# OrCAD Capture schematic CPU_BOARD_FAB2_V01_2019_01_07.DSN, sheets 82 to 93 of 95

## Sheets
82 072 ISOLATOR_2: size B
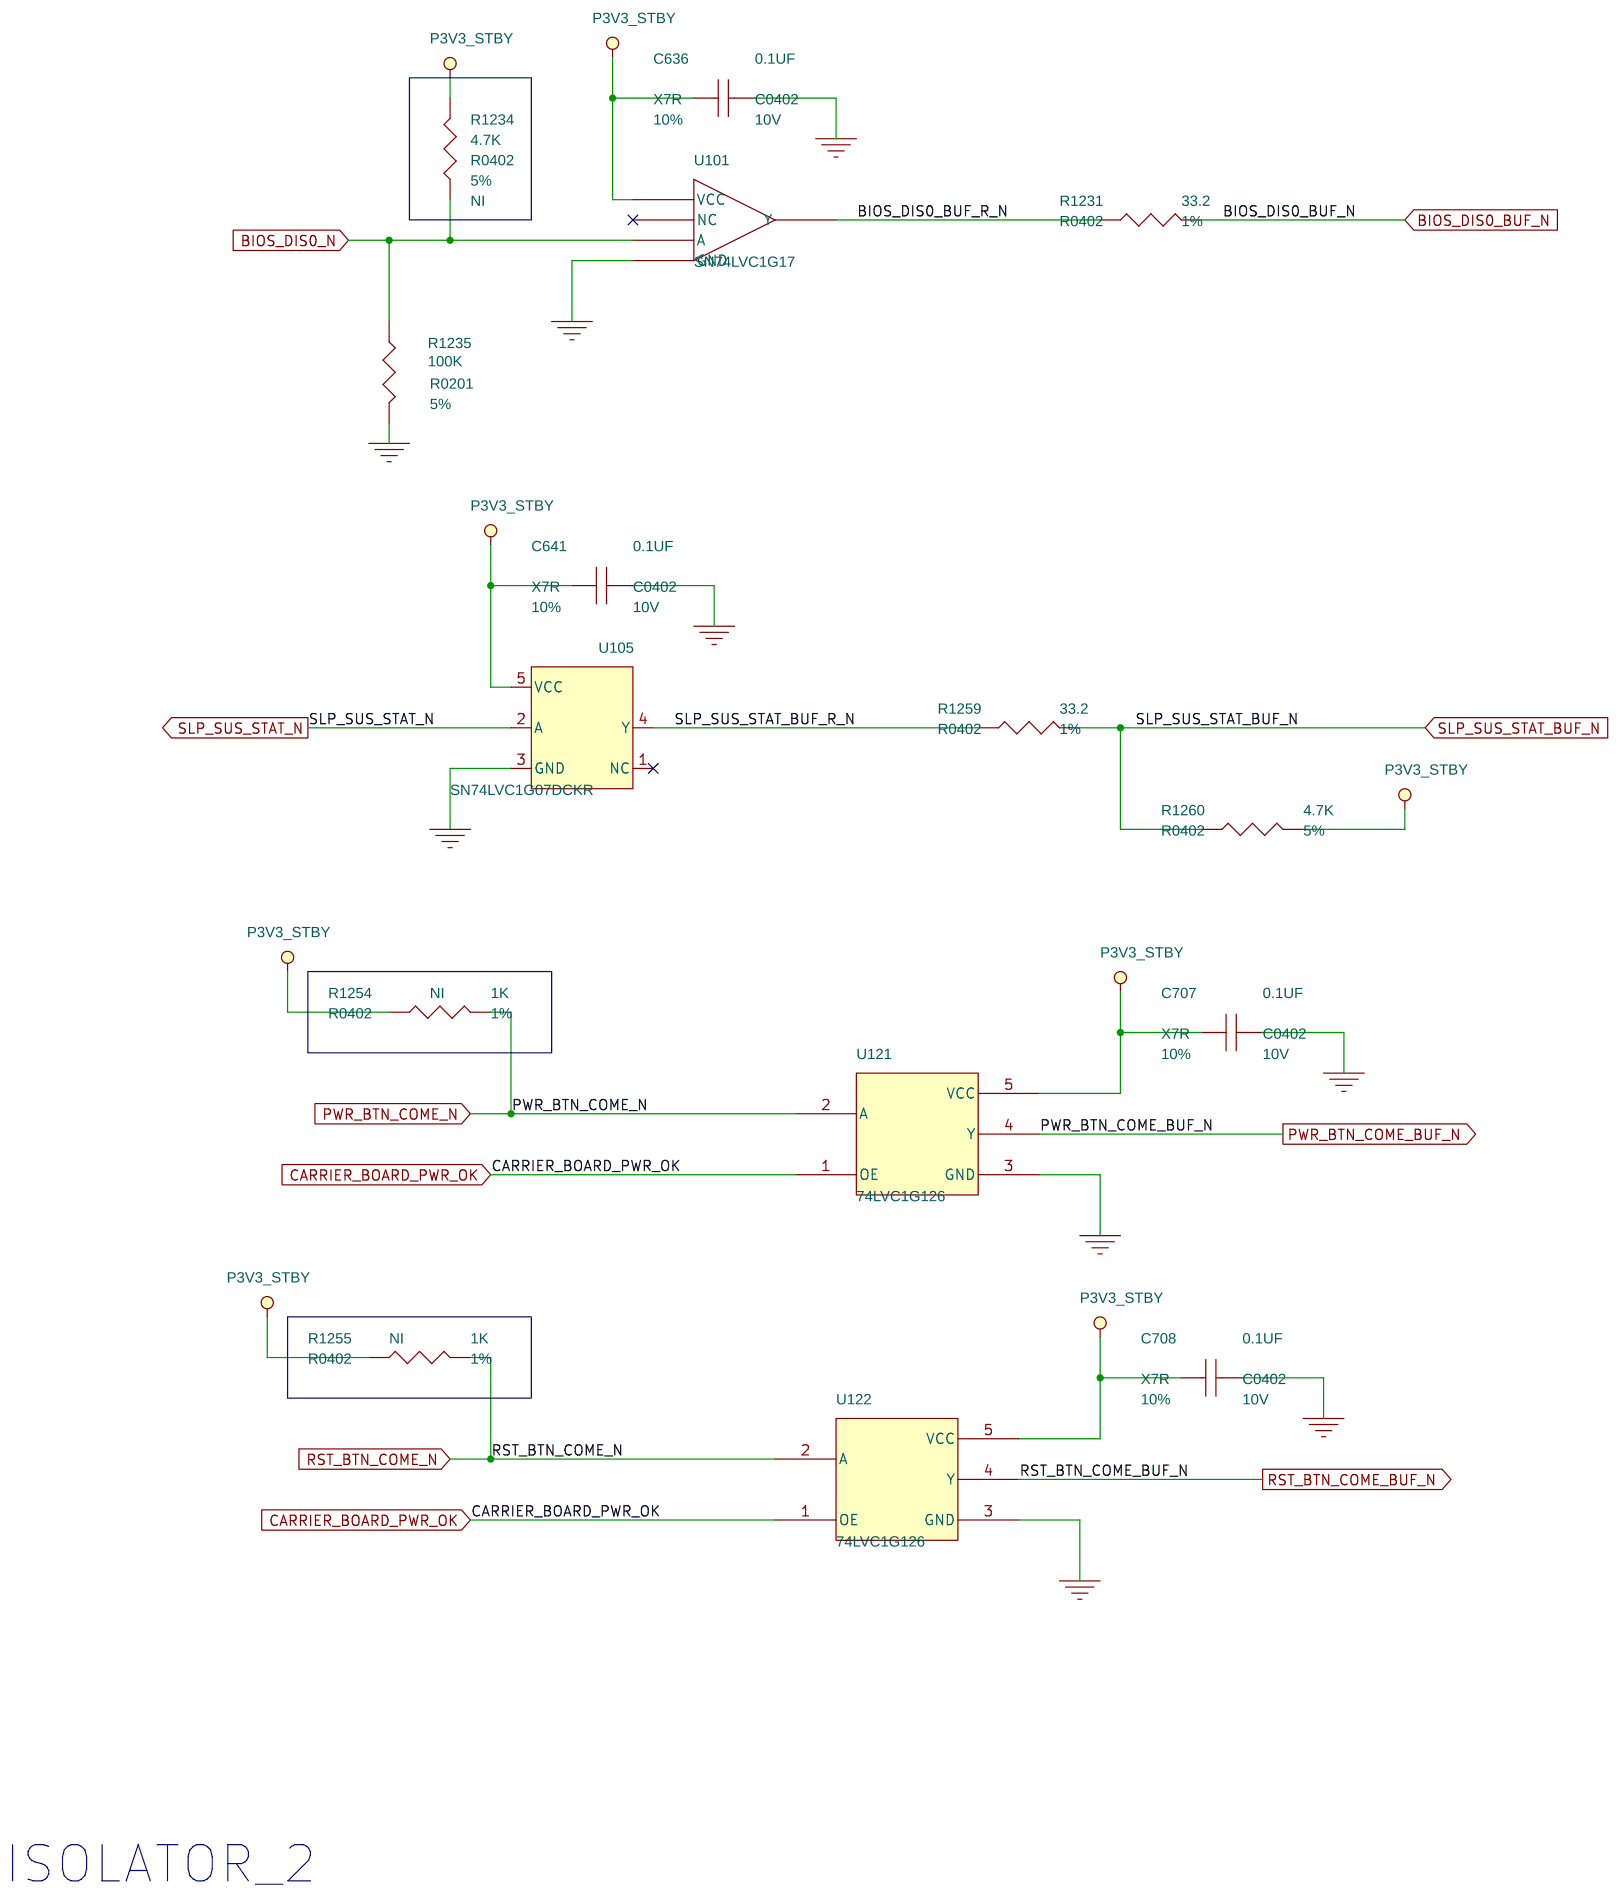
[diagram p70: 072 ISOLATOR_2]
83 077 SCREW: size B
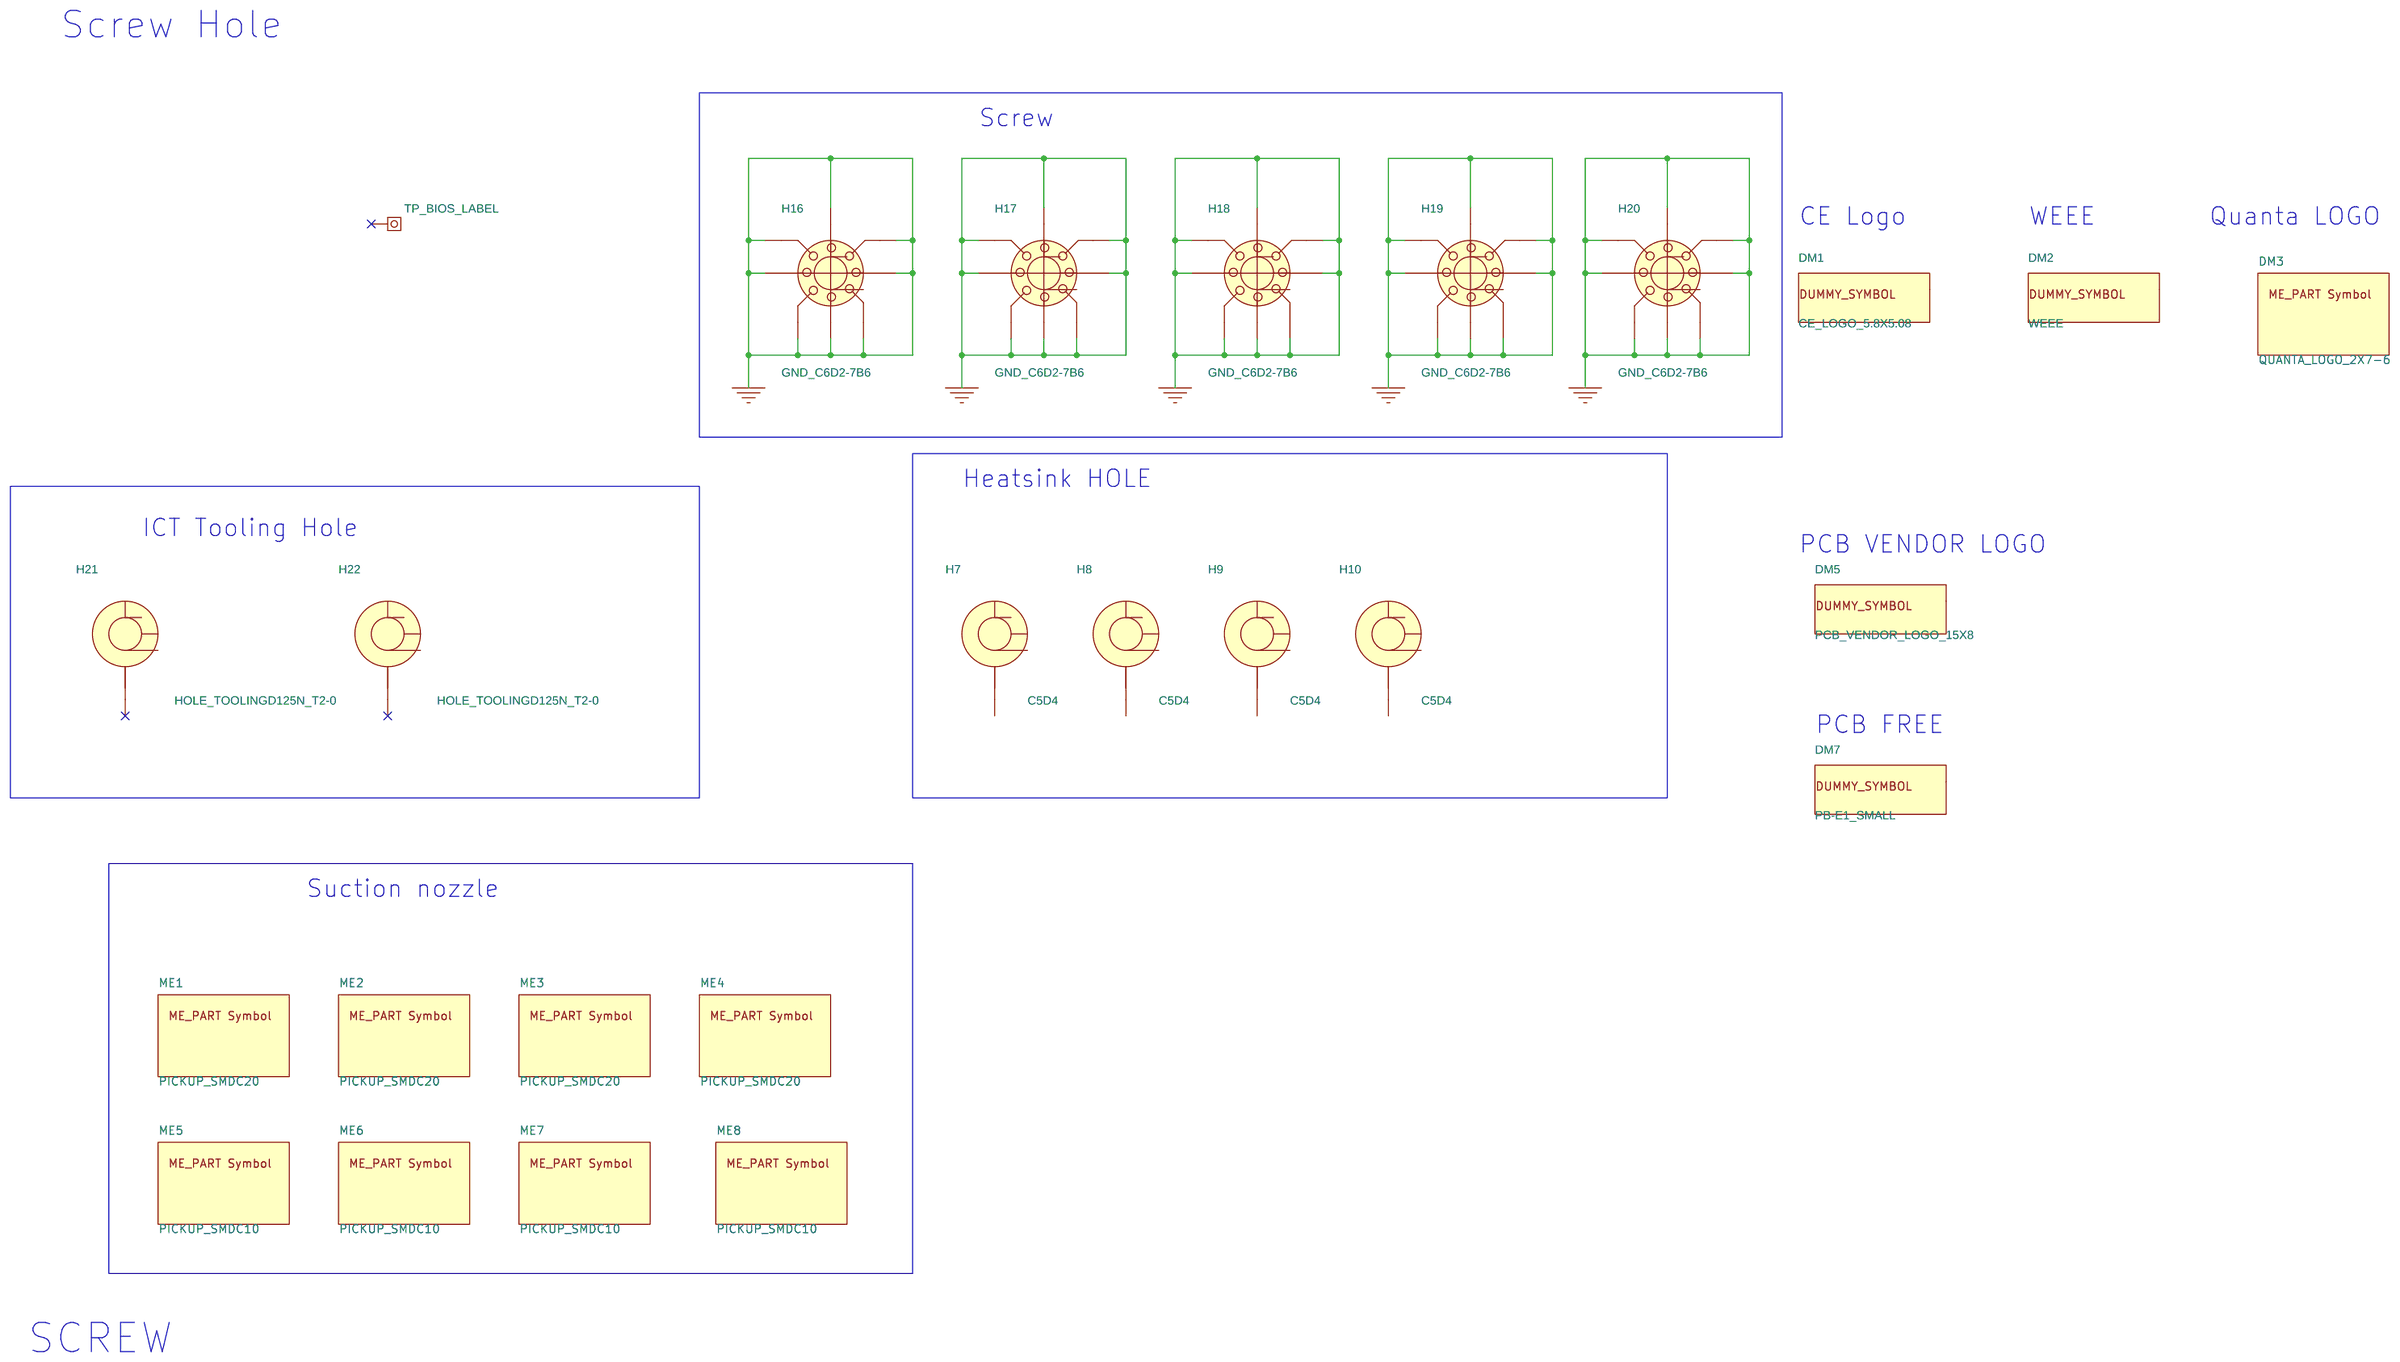
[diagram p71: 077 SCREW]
84 091 P1V05_PCH SWITCH: size B
85 092 BLANK
86 074 POWER SENSING INA230: size B
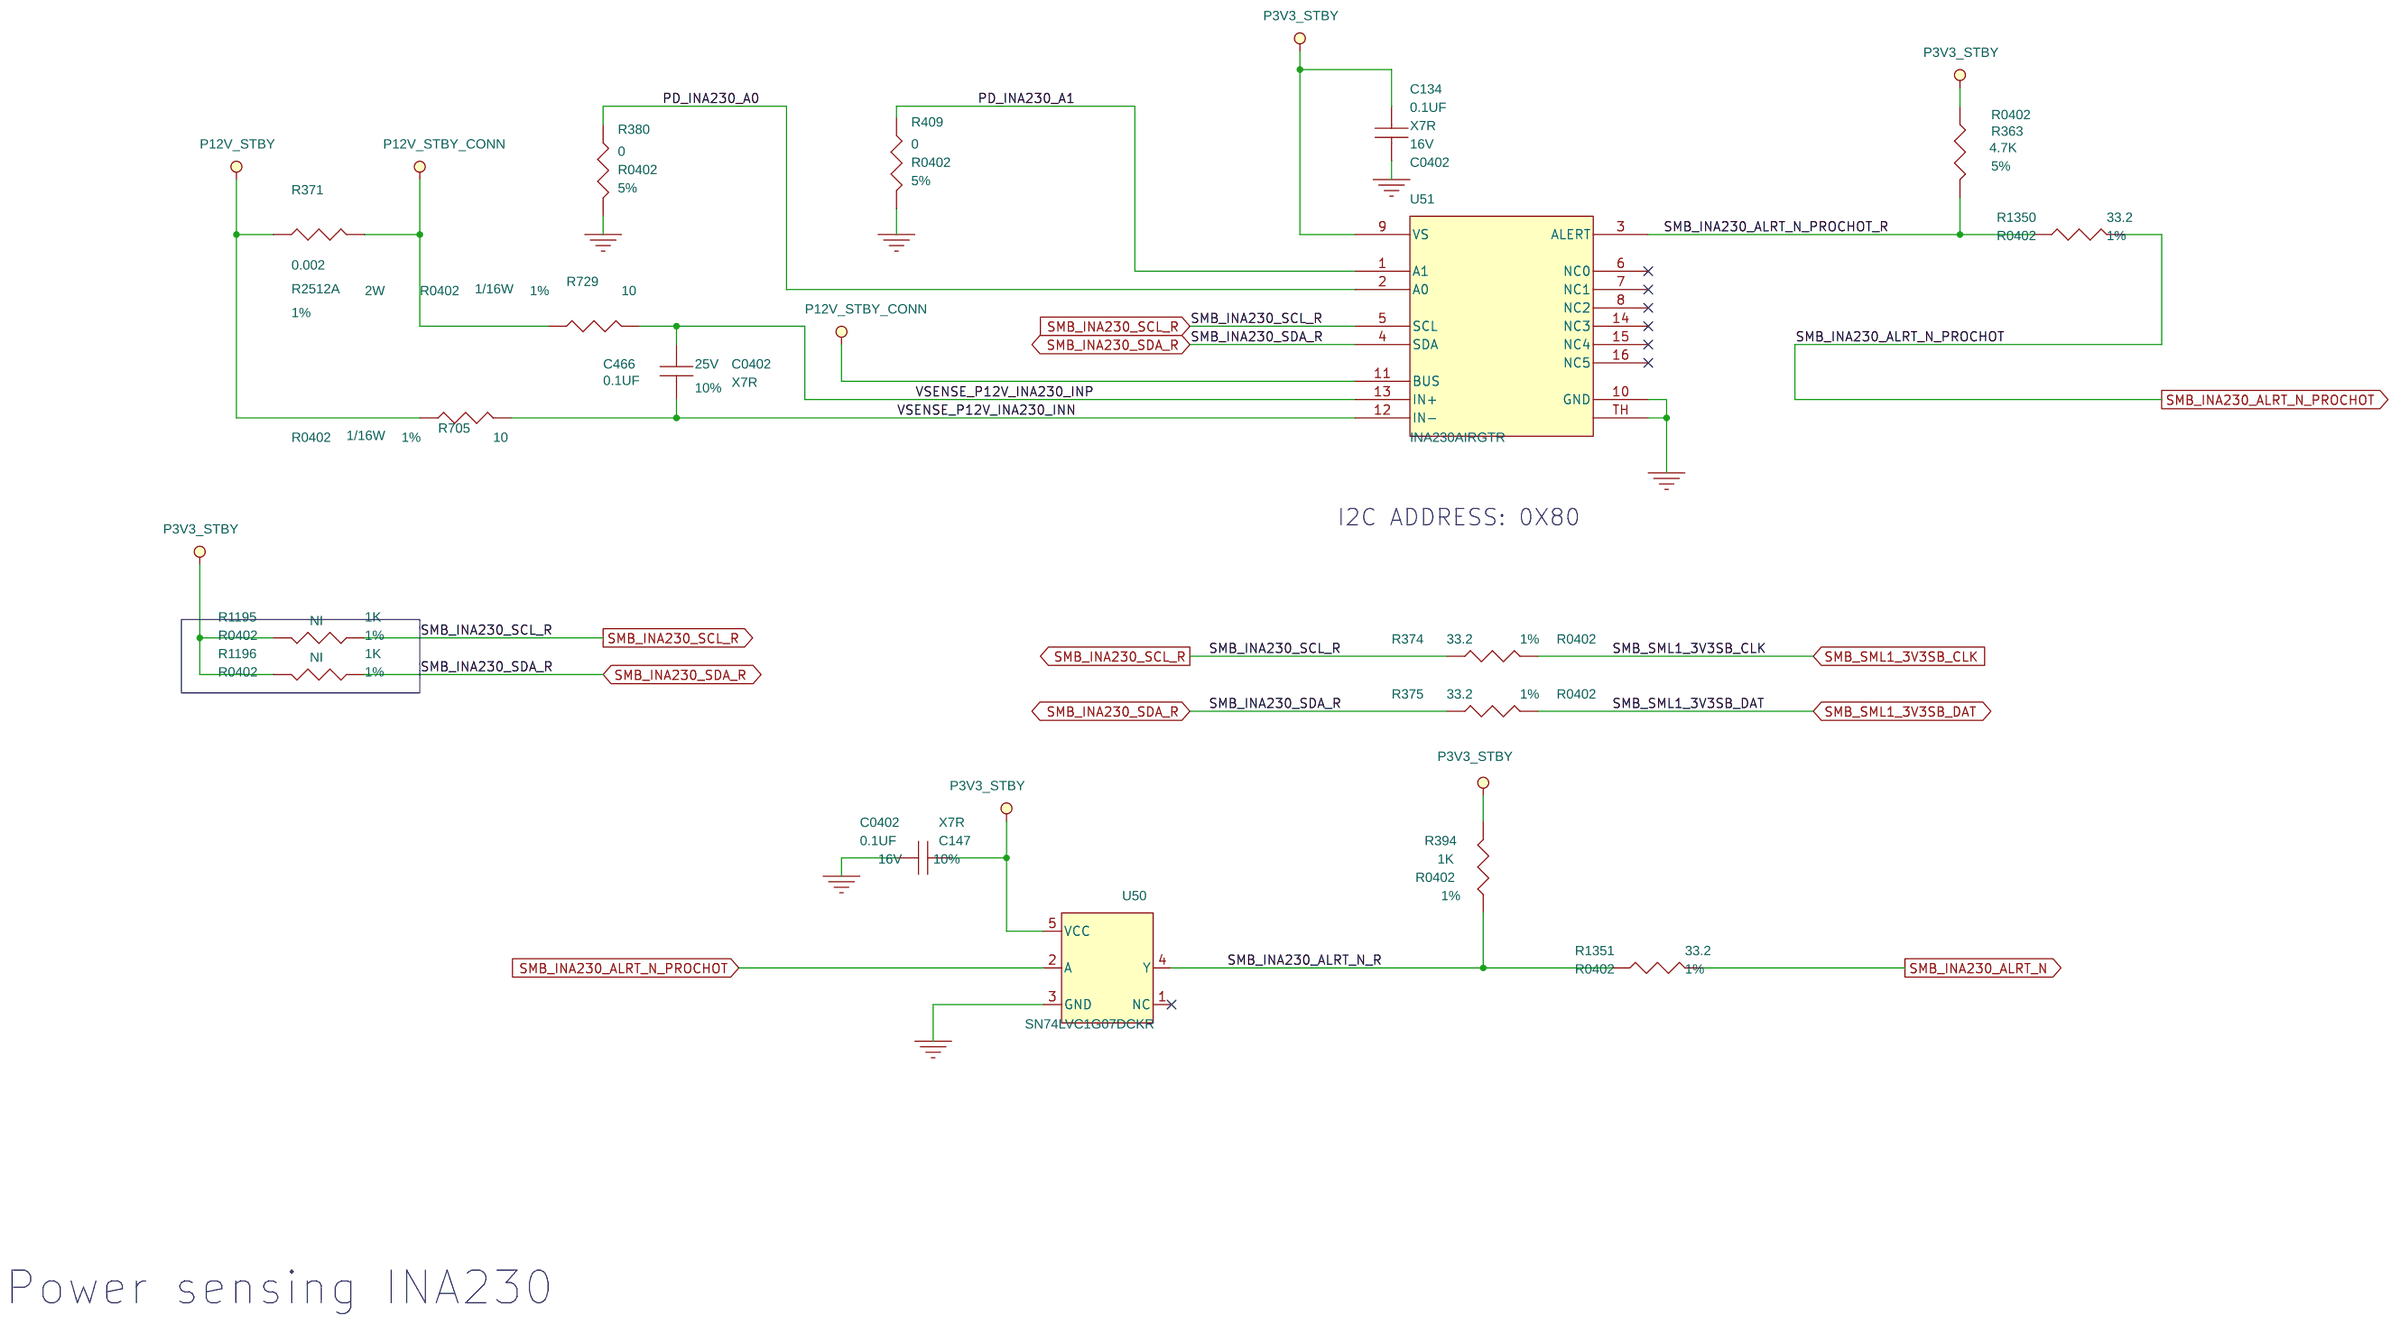
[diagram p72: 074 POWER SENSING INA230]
87 075 I210 GbE PHY PCIE,MDI: size B
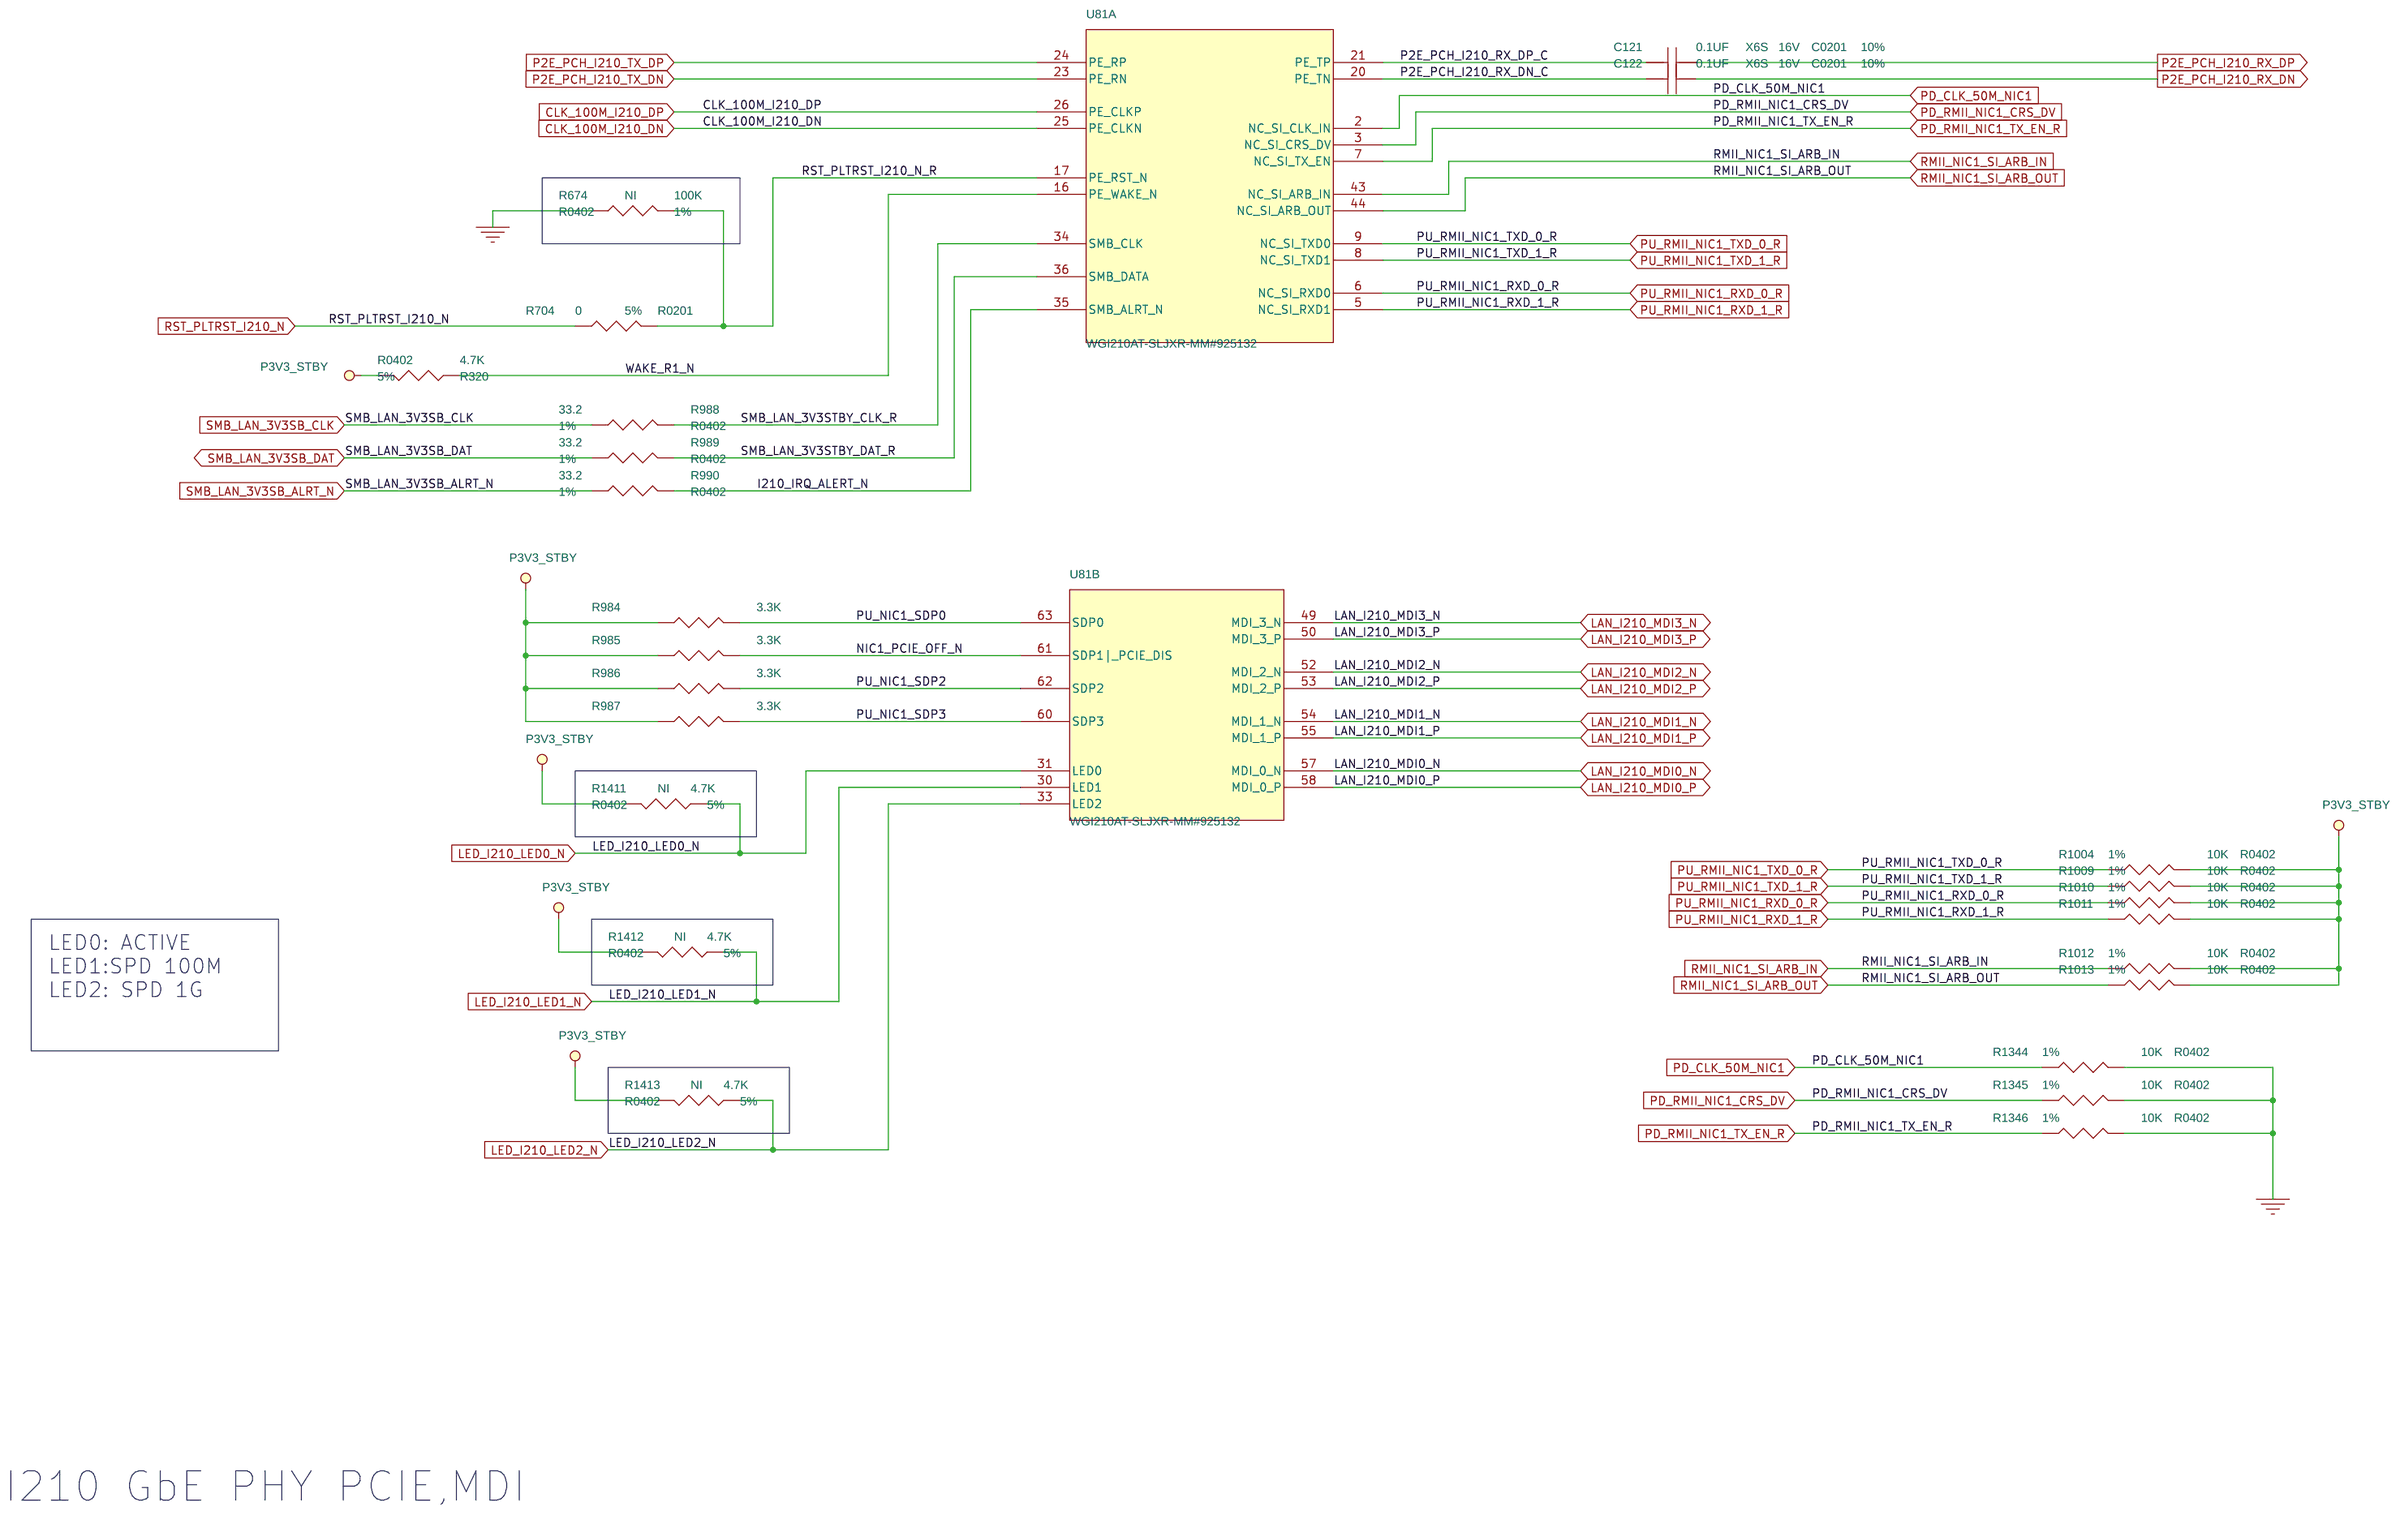
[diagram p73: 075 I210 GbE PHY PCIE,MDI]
88 076 I210 GbE PHY JTAG,SPI,POWER: size B
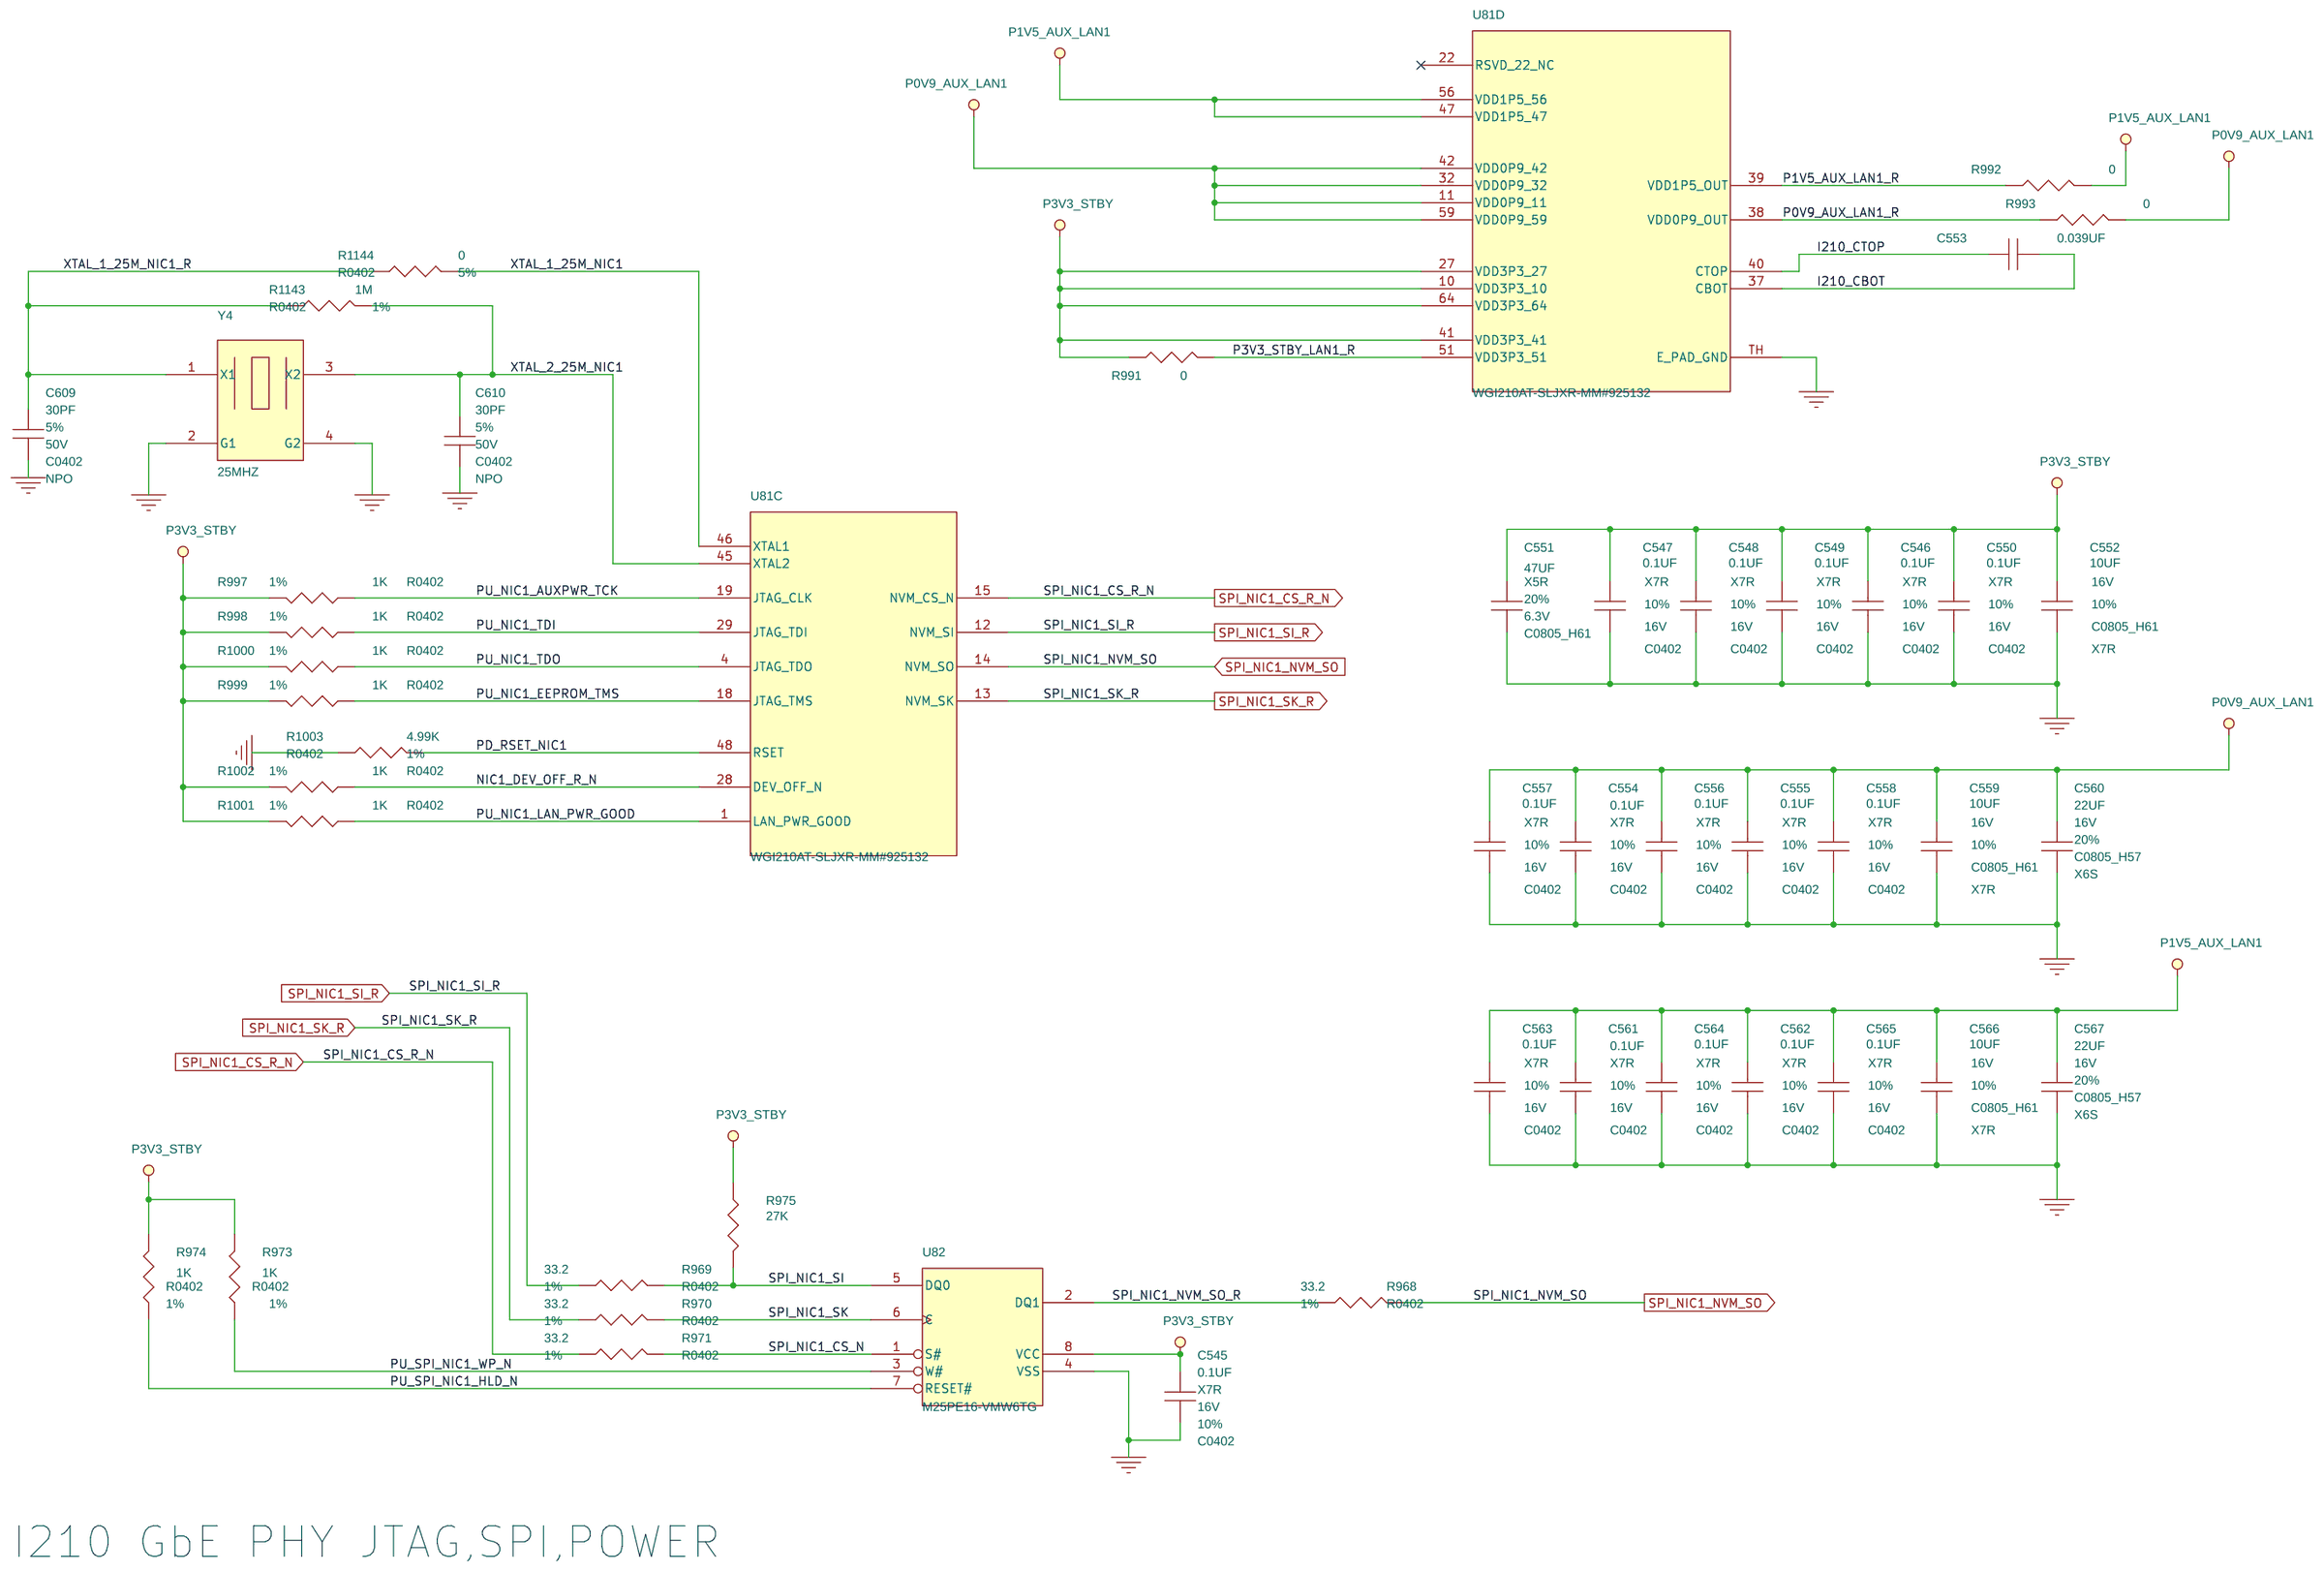
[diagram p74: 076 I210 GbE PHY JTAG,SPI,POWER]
89 093 TP RESERVE FOR ICT: size B
90 007 POWER SEQUENCE DIAGRAM_2
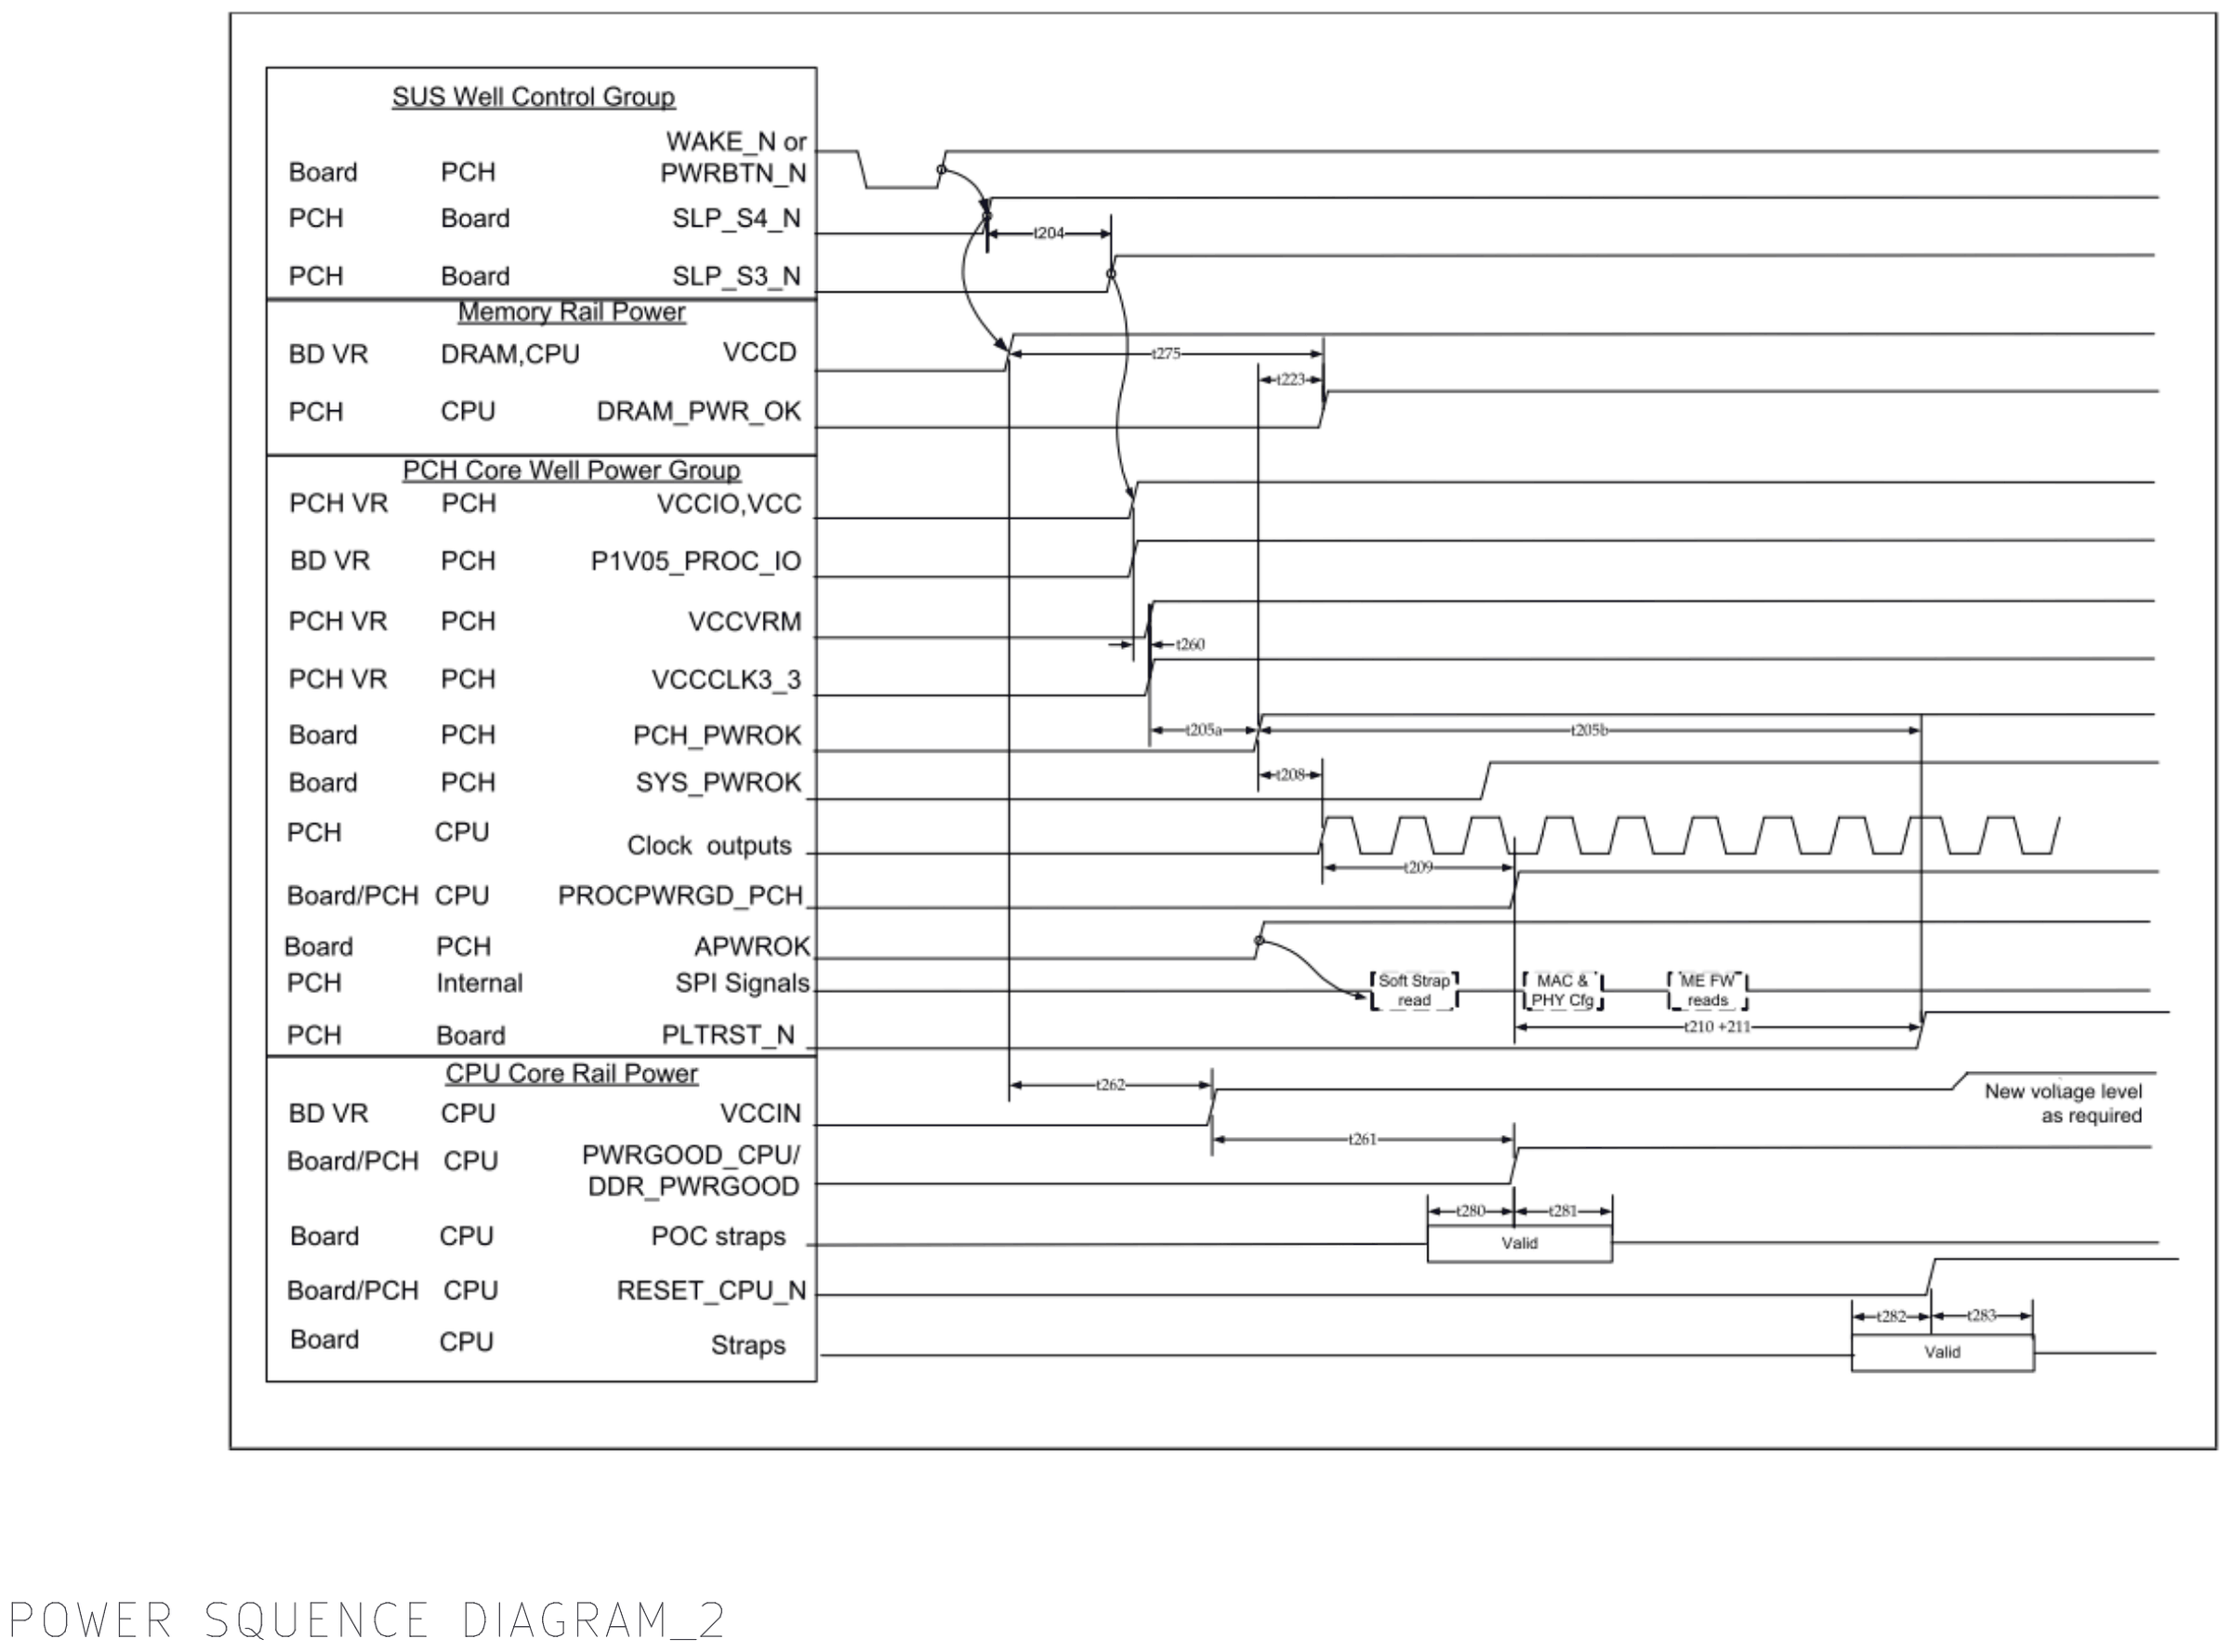
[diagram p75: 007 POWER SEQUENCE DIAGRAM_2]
91 095 BLANK
92 073 MDC/MDIO: size B
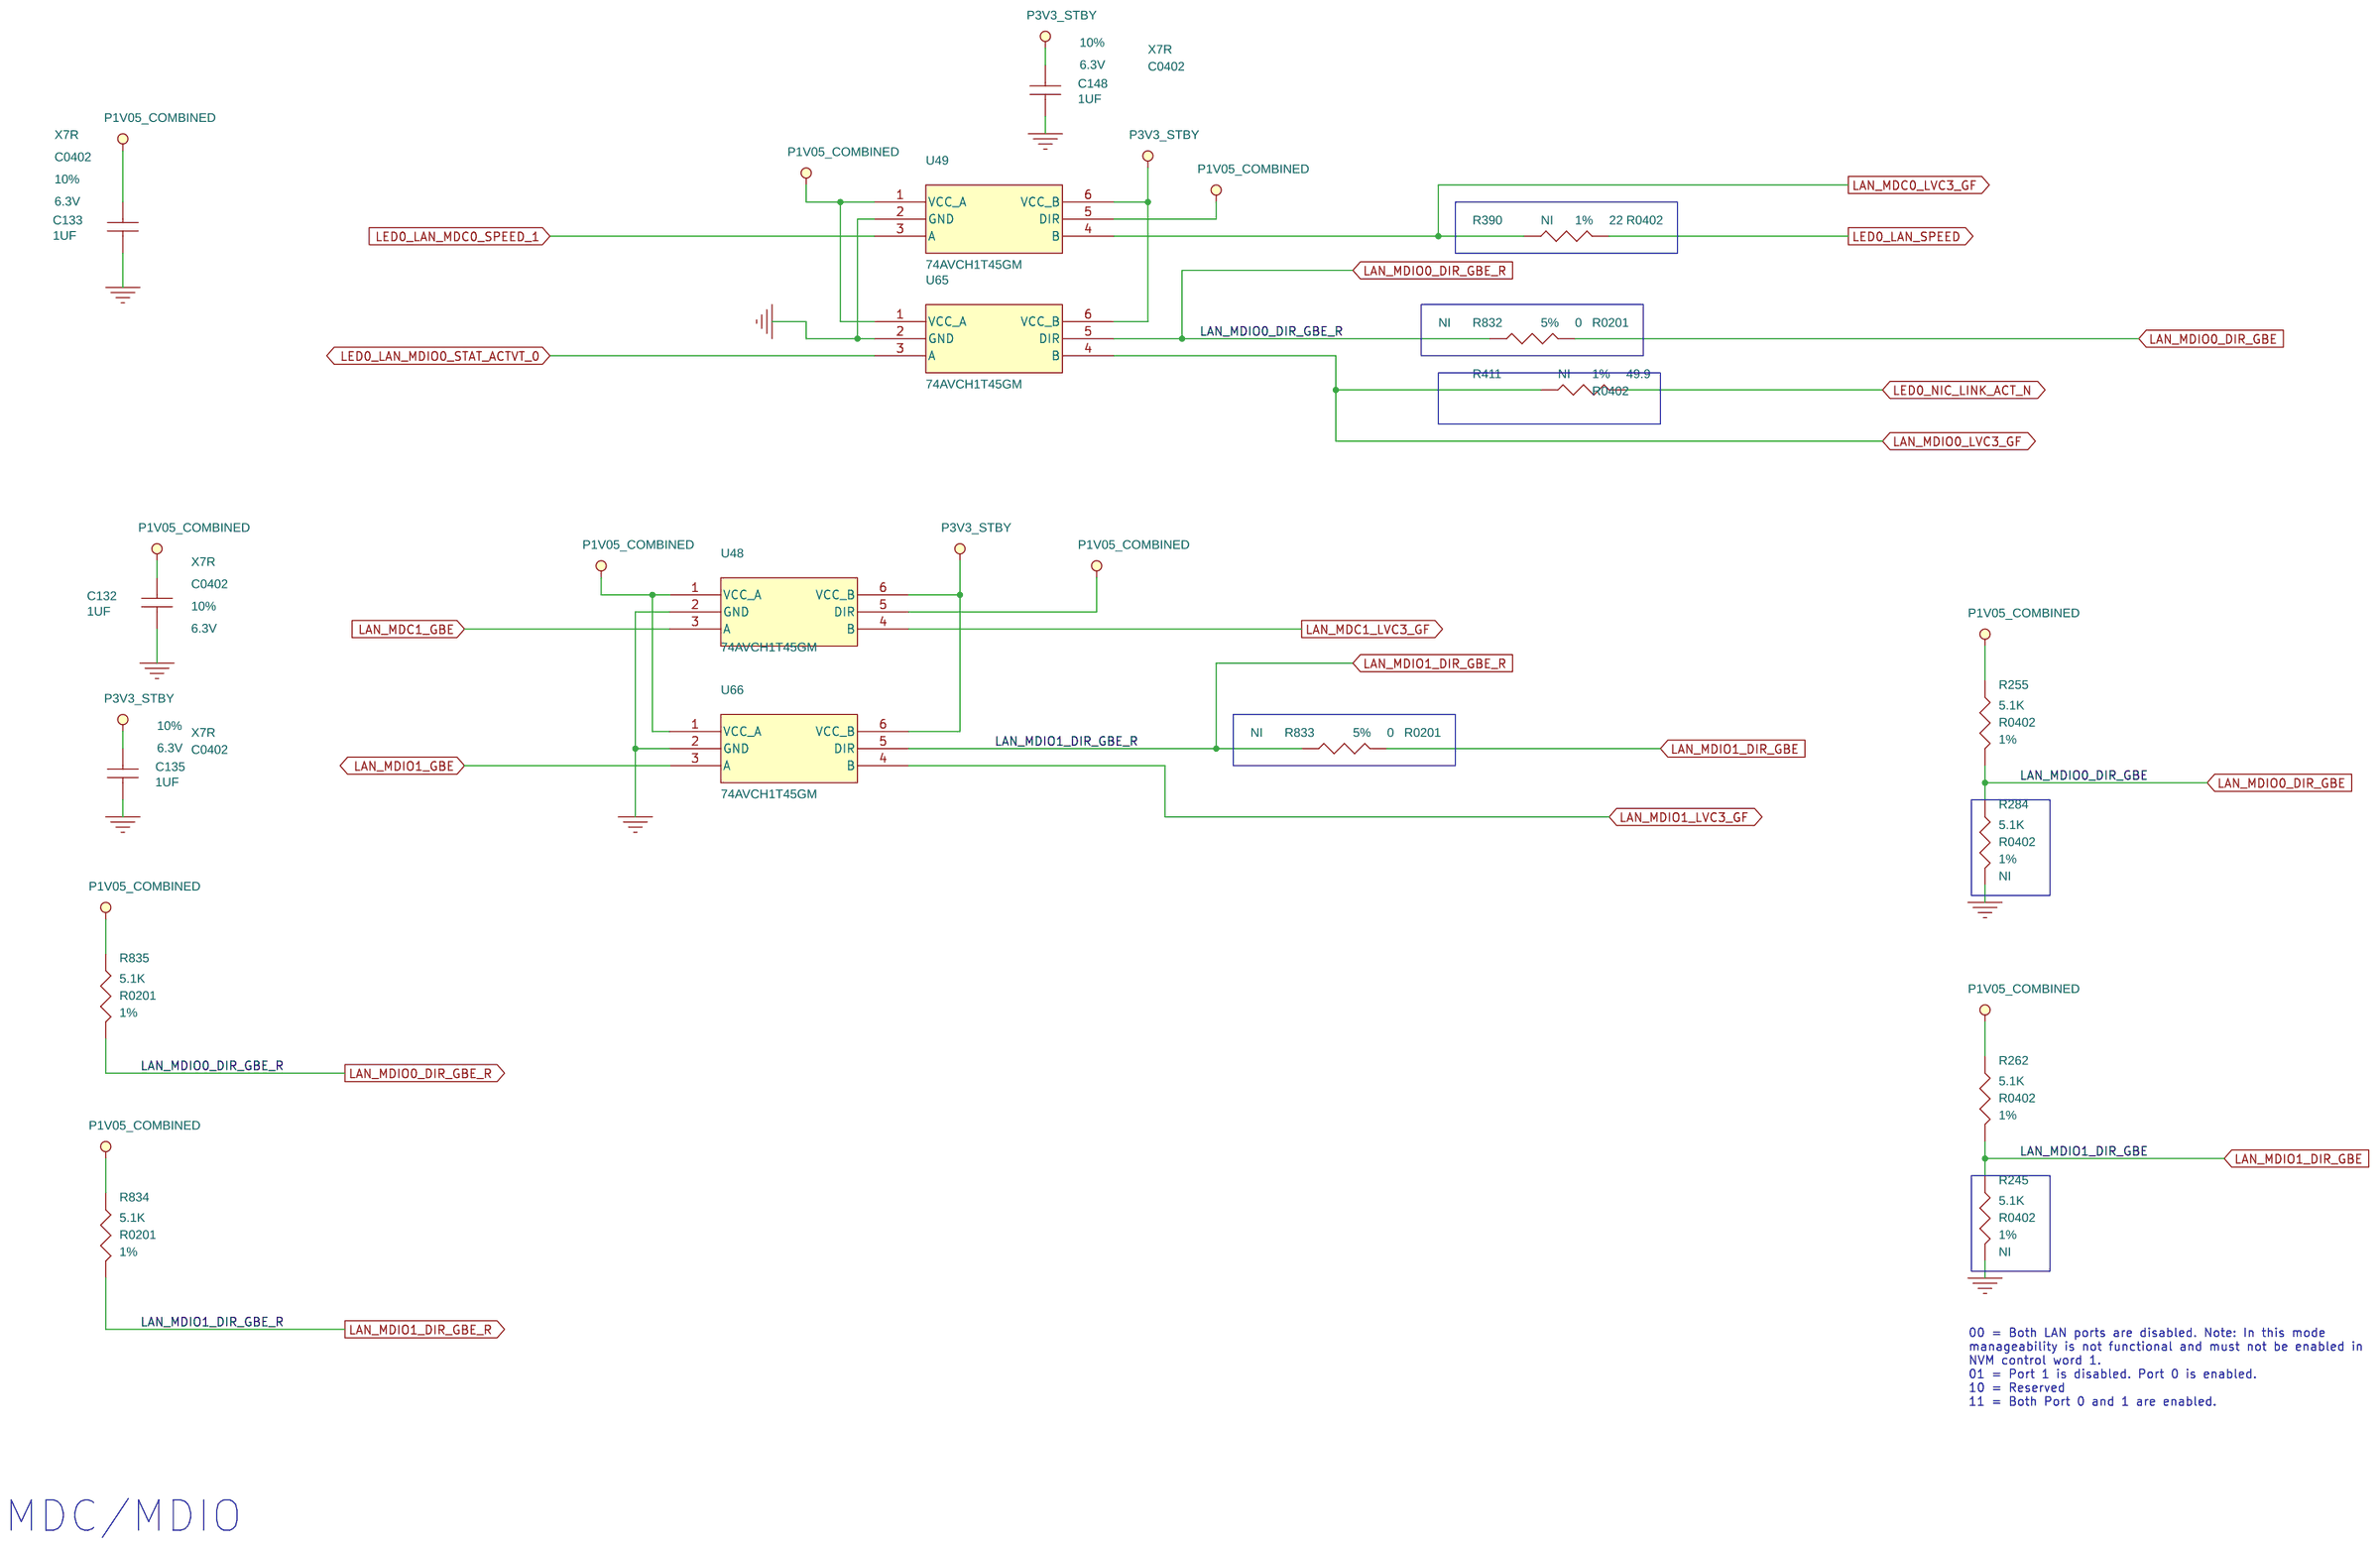
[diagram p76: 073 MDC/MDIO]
93 009 PWRGD/RST DIAGRAM
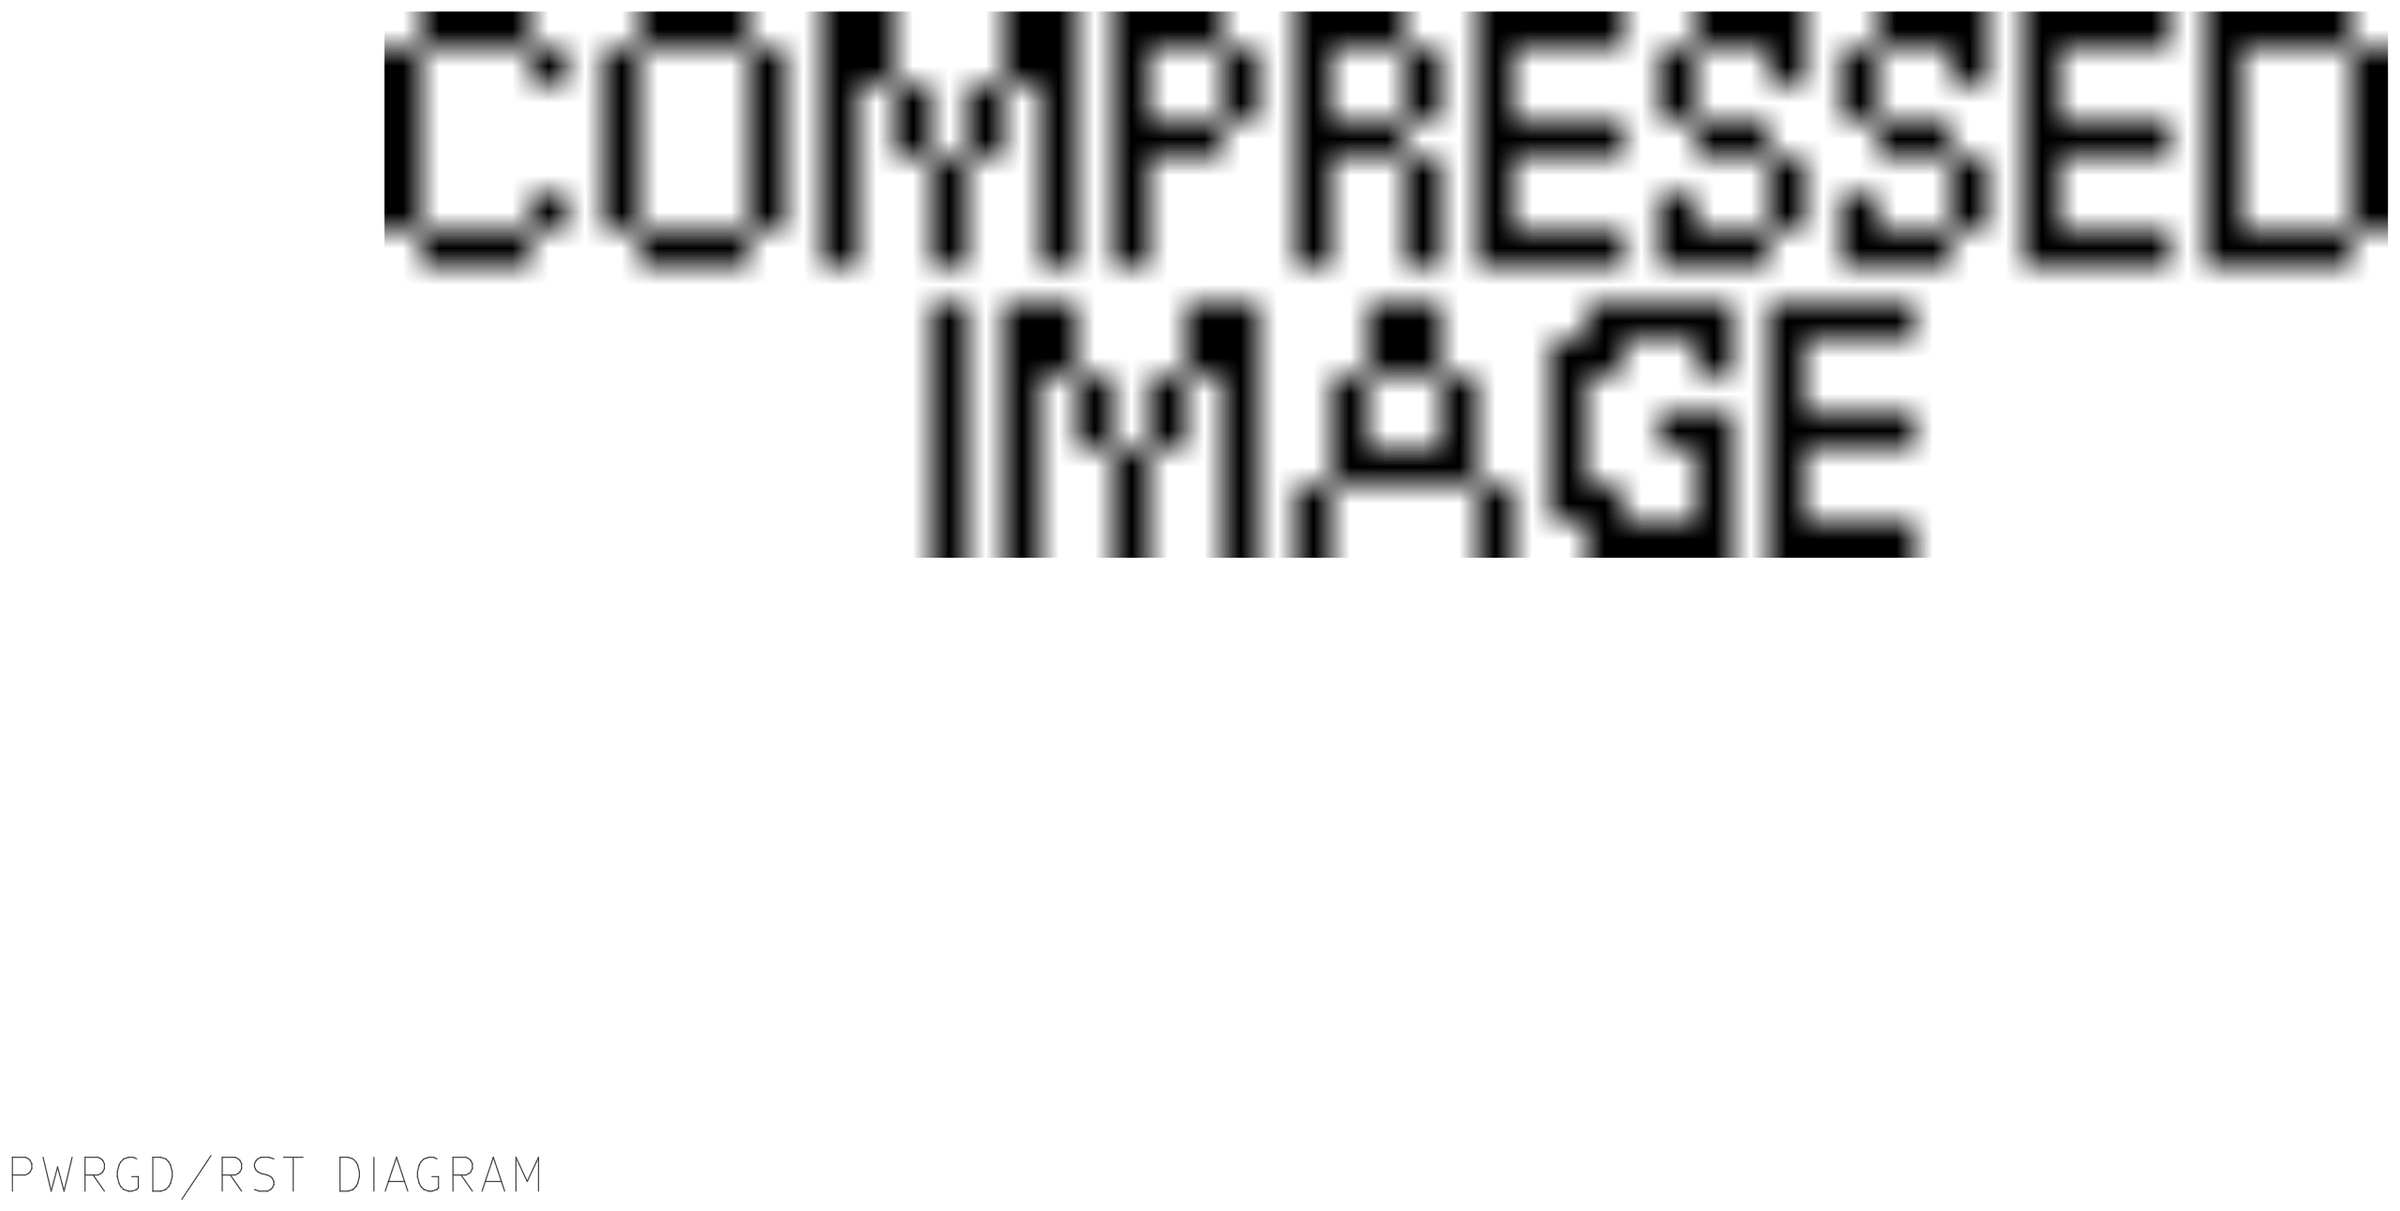
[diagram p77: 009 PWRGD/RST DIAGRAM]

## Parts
sheet 072 ISOLATOR_2
C636  0.1UF  [C0402]
C641  0.1UF  [C0402]
C707  0.1UF  [C0402]
C708  0.1UF  [C0402]
R1231  33.2  [R0402]
R1234  4.7K  [R0402]
R1235  100K  [R0201]
R1254  1K  [R0402]
R1255  1K  [R0402]
R1259  33.2  [R0402]
R1260  4.7K  [R0402]
U101  SN74LVC1G17  [SC70-5]
U105  SN74LVC1G07DCKR  [SC70-5XB]
U121  74LVC1G126  [SOT353_Q]
U122  74LVC1G126  [SOT353_Q]
sheet 073 MDC/MDIO
C132  1UF  [C0402]
C133  1UF  [C0402]
C135  1UF  [C0402]
C148  1UF  [C0402]
R245  5.1K  [R0402]
R255  5.1K  [R0402]
R262  5.1K  [R0402]
R284  5.1K  [R0402]
R390  22  [R0402]
R411  49.9  [R0402]
R832  0  [R0201]
R833  0  [R0201]
R834  5.1K  [R0201]
R835  5.1K  [R0201]
U48  74AVCH1T45GM  [SOT886]
U49  74AVCH1T45GM  [SOT886]
U65  74AVCH1T45GM  [SOT886]
U66  74AVCH1T45GM  [SOT886]
sheet 074 POWER SENSING INA230
C134  0.1UF  [C0402]
C147  0.1UF  [C0402]
C466  0.1UF  [C0402]
R363  4.7K  [R0402]
R371  0.002  [R2512A]
R374  33.2  [R0402]
R375  33.2  [R0402]
R380  0  [R0402]
R394  1K  [R0402]
R409  0  [R0402]
R705  10  [R0402]
R729  10  [R0402]
R1195  1K  [R0402]
R1196  1K  [R0402]
R1350  33.2  [R0402]
R1351  33.2  [R0402]
U50  SN74LVC1G07DCKR  [SC70-5XB]
U51  INA230AIRGTR  [QFN16_THXI]
sheet 075 I210 GbE PHY PCIE,MDI
C121  0.1UF  [C0201]
C122  0.1UF  [C0201]
R320  4.7K  [R0402]
R674  100K  [R0402]
R704  0  [R0201]
R984  3.3K  [R0402]
R985  3.3K  [R0402]
R986  3.3K  [R0402]
R987  3.3K  [R0402]
R988  33.2  [R0402]
R989  33.2  [R0402]
R990  33.2  [R0402]
R1004  10K  [R0402]
R1009  10K  [R0402]
R1010  10K  [R0402]
R1011  10K  [R0402]
R1012  10K  [R0402]
R1013  10K  [R0402]
R1344  10K  [R0402]
R1345  10K  [R0402]
R1346  10K  [R0402]
R1411  4.7K  [R0402]
R1412  4.7K  [R0402]
R1413  4.7K  [R0402]
U81  WGI210AT-SLJXR-MM#925132  [QFN64_THXK]  (sections A,B,C,D)
sheet 076 I210 GbE PHY JTAG,SPI,POWER
C545  0.1UF  [C0402]
C546  0.1UF  [C0402]
C547  0.1UF  [C0402]
C548  0.1UF  [C0402]
C549  0.1UF  [C0402]
C550  0.1UF  [C0402]
C551  47UF  [C0805_H61]
C552  10UF  [C0805_H61]
C553  0.039UF  [C0603]
C554  0.1UF  [C0402]
C555  0.1UF  [C0402]
C556  0.1UF  [C0402]
C557  0.1UF  [C0402]
C558  0.1UF  [C0402]
C559  10UF  [C0805_H61]
C560  22UF  [C0805_H57]
C561  0.1UF  [C0402]
C562  0.1UF  [C0402]
C563  0.1UF  [C0402]
C564  0.1UF  [C0402]
C565  0.1UF  [C0402]
C566  10UF  [C0805_H61]
C567  22UF  [C0805_H57]
C609  30PF  [C0402]
C610  30PF  [C0402]
R968  33.2  [R0402]
R969  33.2  [R0402]
R970  33.2  [R0402]
R971  33.2  [R0402]
R973  1K  [R0402]
R974  1K  [R0402]
R975  27K  [R0402]
R991  0  [R0603]
R992  0  [R0603]
R993  0  [R0603]
R997  1K  [R0402]
R998  1K  [R0402]
R999  1K  [R0402]
R1000  1K  [R0402]
R1001  1K  [R0402]
R1002  1K  [R0402]
R1003  4.99K  [R0402]
R1143  1M  [R0402]
R1144  0  [R0402]
U82  M25PE16-VMW6TG  [SOIC8_6-22_H99]
Y4  25MHZ  [X_4S_8Z25000020_2-5X2]
sheet 077 SCREW
DM1  CE_LOGO_5.8X5.08  [CE]
DM2  WEEE  [WEEE]
DM3  QUANTA_LOGO_2X7-6  [QUANTA_LOGO_2X7-6]
DM5  PCB_VENDOR_LOGO_15X8  [PCB_VENDOR_LOGO_15X8]
DM7  PB-E1_SMALL  [PB-E1_SMALL]
H7  C5D4  [HOLE_C5D4]
H8  C5D4  [HOLE_C5D4]
H9  C5D4  [HOLE_C5D4]
H10  C5D4  [HOLE_C5D4]
H16  GND_C6D2-7B6  [GND_C6D2-7B6]
H17  GND_C6D2-7B6  [GND_C6D2-7B6]
H18  GND_C6D2-7B6  [GND_C6D2-7B6]
H19  GND_C6D2-7B6  [GND_C6D2-7B6]
H20  GND_C6D2-7B6  [GND_C6D2-7B6]
H21  HOLE_TOOLINGD125N_T2-0  [HOLE_TOOLINGD125N_T2-0]
H22  HOLE_TOOLINGD125N_T2-0  [HOLE_TOOLINGD125N_T2-0]
ME1  PICKUP_SMDC20  [PICKUP_SMDC20]
ME2  PICKUP_SMDC20  [PICKUP_SMDC20]
ME3  PICKUP_SMDC20  [PICKUP_SMDC20]
ME4  PICKUP_SMDC20  [PICKUP_SMDC20]
ME5  PICKUP_SMDC10  [PICKUP_SMDC10]
ME6  PICKUP_SMDC10  [PICKUP_SMDC10]
ME7  PICKUP_SMDC10  [PICKUP_SMDC10]
ME8  PICKUP_SMDC10  [PICKUP_SMDC10]
TP_BIOS_LABEL  TP  [TP26D10]
sheet 091 P1V05_PCH SWITCH
C82  100NF  [C0402]
C88  0.1UF  [C0402]
C89  0.1UF  [C0402]
C95  0.1UF  [C0402]
R144  10K  [R0402]
R145  0  [R0402]
R172  10K  [R0402]
R1163  33.2  [R0402]
U23  BSZ017NE2LS5I  [TSDSON3_0-65_3-3X3-3]
U26  SLG55021-200010VTR  [TDFN8_THXE]
sheet 093 TP RESERVE FOR ICT
R861  0  [R0201]
R866  0  [R0201]
R867  0  [R0201]
R868  0  [R0201]
R869  0  [R0201]
R870  0  [R0201]
R871  0  [R0201]
R872  0  [R0402]
R873  0  [R0402]
R874  0  [R0402]
R875  0  [R0402]
R876  0  [R0402]
R877  0  [R0402]
R878  0  [R0402]
R879  0  [R0402]
R880  0  [R0402]
R881  0  [R0402]
R882  0  [R0402]
R883  0  [R0402]
R884  0  [R0402]
R885  0  [R0402]
R886  0  [R0402]
R887  0  [R0402]
R888  0  [R0402]
R889  0  [R0402]
R890  0  [R0402]
R891  0  [R0402]
R892  0  [R0402]
R893  0  [R0402]
R894  0  [R0402]
R895  0  [R0402]
R896  0  [R0402]
R897  0  [R0402]
R898  0  [R0402]
R899  0  [R0402]
R900  0  [R0402]
R901  0  [R0402]
R902  0  [R0402]
R903  0  [R0402]
R904  0  [R0402]
R905  0  [R0402]
R906  0  [R0402]
R907  0  [R0402]
R908  0  [R0603]
R909  0  [R0805]
R910  0  [R0805]
R911  0  [R0805]
R912  0  [R0805]
R913  0  [R0805]
R914  0  [R0805]
R915  0  [R1206]
R916  0  [R1206]
R917  0  [R1206]
R918  0  [R0201]
R919  0  [R0201]
R920  0  [R0201]
R921  0  [R0201]
R922  0  [R0201]
R923  0  [R0201]
R924  0  [R0201]
R925  0  [R0201]
R926  0  [R0402]
R927  0  [R0402]
R928  0  [R0402]
R929  0  [R0402]
R930  0  [R0402]
R931  0  [R0402]
R932  0  [R0402]
R933  0  [R0402]
R934  0  [R0402]
R935  0  [R0402]
R936  0  [R0402]
R937  0  [R0402]
R938  0  [R0402]
R939  0  [R0402]
R940  0  [R0402]
R941  0  [R0402]
R942  0  [R0402]
R943  0  [R0402]
R944  0  [R0402]
R945  0  [R0402]
R946  0  [R0402]
R947  0  [R0402]
R948  0  [R0402]
R949  0  [R0402]
R950  0  [R0402]
R951  0  [R0402]
R952  0  [R0402]
R953  0  [R0603]
R954  0  [R0603]
R955  0  [R0603]
R956  0  [R0603]
R957  0  [R0603]
R958  0  [R0603]
R959  0  [R0603]
R960  0  [R0603]
R961  0  [R0603]
R962  0  [R0805]
R963  0  [R0805]
R964  0  [R0805]
R965  0  [R0805]
R966  0  [R1206]
R967  0  [R1206]

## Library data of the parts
C636 C641 C707 C708 = CAP_NP: CAP CHIP 0.1U 10V(+-10%.X7R.0402); CLASS: DISCRETE; CMPLS_LVL: EP; Data: RHT_LF_CAP SERIES-1.pdf; From_pj: S82-ICE; Lifecycle: Comp-Approve; MATERIAL: X7R; Manuf_PN: GRM155R71A104K; Manuf_name: "MURATA ERIE N.A. INC TAIWAN BRANCH Okayama Murata Mfg.Co..Ltd.Wakura Murata Mfg; Manuftr: MUR; Part_Type: *LF_C0402; Standard: ##; Status: Preferred; TOLERANCE: 10%; VOLTAGE: 10V; fp_ECN: 0402 SERIES_LL34.xls
R968-R971 R988-R990 R1163 R1231 R1259 R1350 R1351 = R: RES CHIP 33.2 1/16W +-1%(0402); CLASS: DISCRETE; CMPLS_LVL: EP; Data: CYN_LF_RL SERIES.pdf; From_pj: A06-EDISON; Lifecycle: Comp-Approve; MATERIAL: CHIP; Manuf_PN: RR0510S-33R2-FN; Manuf_name: CYNTEC CO.. LTD.; Manuftr: CYN; Part_Type: *LF_Resistor; TOLERANCE: 1%; WATTAGE: 1/16W; fp_ECN: 0402 SERIES_LL34.xls
R1234 = R: RES CHIP 4.7K 1/16W +-5% (0402); CLASS: DISCRETE; CMPLS_LVL: EP; Data: WTC_LF_WR SERIES.pdf; Lifecycle: Comp-Approve; MATERIAL: CHIP; Manuf_PN: RR0510S-472-JN; Manuf_name: CYNTEC CO.. LTD.; Manuftr: CYN; Not_insert: NI; Part_Type: *LF_Resistor; Status: Preferred; TOLERANCE: 5%; WATTAGE: 1/16W; fp_ECN: 0402 SERIES_LL34.xls
R1235 = R: RES CHIP 100K(1/20W,+-5%,0201); CLASS: DISCRETE; CMPLS_LVL: EP(V1); Data: CYN_RL SERIES_revB0.pdf; From_pj: GD1-JOSH; Lifecycle: Comp-Approve; MATERIAL: CHIP; Manuf_PN: RR0306S-104-JN; Manuf_name: CYNTEC CO., LTD.; Manuftr: CYN; Part_Type: *LF_Resistor; RD_CMPLS_LVL: EP(V1); TOLERANCE: 5%; WATTAGE: 1/20W; fp_ECN: DCN-all 0201 RCL part.doc
R1195 R1196 R1254 R1255 = R: RES CHIP 1K 1/16W +-1% (0402); CLASS: DISCRETE; CMPLS_LVL: EP; Data: WTC_LF_WR SERIES.pdf; Lifecycle: Comp-Approve; MATERIAL: CHIP; Manuf_PN: RR0510S-102-FN; Manuf_name: CYNTEC CO.. LTD.; Manuftr: CYN; Not_insert: NI; Part_Type: *LF_Resistor; Status: Preferred; TOLERANCE: 1%; WATTAGE: 1/16W; fp_ECN: 0402 SERIES_LL34.xls
R363 R1260 = R: RES CHIP 4.7K 1/16W +-5% (0402); CLASS: DISCRETE; CMPLS_LVL: EP; Data: WTC_LF_WR SERIES.pdf; Lifecycle: Comp-Approve; MATERIAL: CHIP; Manuf_PN: RR0510S-472-JN; Manuf_name: CYNTEC CO.. LTD.; Manuftr: CYN; Part_Type: *LF_Resistor; Status: Preferred; TOLERANCE: 5%; WATTAGE: 1/16W; fp_ECN: 0402 SERIES_LL34.xls
U101 = 74LVC1G04_1: IC(5P) SN74LVC1G17DCKR (SC-70); CLASS: IC; CMPLS_LVL: EP; Data: TIC_SN74LVC1G17DCKR.pdf; From_pj: S90-ROX; Lifecycle: Comp-Approve; MATERIAL: IC; Manuf_PN: SN74LVC1G17DCKR; Manuf_name: "TEXAS INSTRUMENTS SUPPLY CO.."; Manuftr: TIC; Part_Type: *LF_Chipset; Standard: Potential
U50 U105 = SN74LVC1G07: IC OTHER(5P)SN74LVC1G07DCKR(SOT); CLASS: IC; CMPLS_LVL: EP(V1); Data: TIC_SN74LVC1G07DCKR.pdf; From_pj: S50-STEVE; Lifecycle: Comp-Approve; MATERIAL: IC; Manuf_name: TEXAS INSTRUMENTS SUPPLY CO..; Manufacturer: TIC; Manuftr: TIC; Part_Type: *LF_Chipset; RD_CMPLS_LVL: EP(V1); Standard: Potential
U121 U122 = 74LVC1G126: IC(5P) 74LVC1G126GW (SC-88A) EP; CLASS: IC; CMPLS_LVL: EP; Data: PHI_74LVC1G126.pdf; From_pj: S90-ROX; Lifecycle: Comp-Approve; MATERIAL: IC; Manuf_PN: 74LVC1G126GW; Manuf_name: PHILIPS TAIWAN LTD..; Manuftr: PHI; Part_Type: *LF_Chipset
C132 C133 C135 C148 = CAP_NP: CAP CHIP 1U.6.3V(+-10%.X7R.0402); CLASS: DISCRETE; CMPLS_LVL: EP(V1); Data: MKP_LF_CAP SERIES.pdf; From_pj: T94-JEFF; Lifecycle: Comp-Approve; MATERIAL: X7R; Manuf_PN: MAG02X7R0J105K; Manuf_name: Matsuki Precision Ceramic Co.. Ltd.Matsuki Polymer Technology Co.. Ltd.; Manuftr: MKP; Part_Type: *LF_C0402; RD_CMPLS_LVL: EP(V1); TOLERANCE: 10%; VOLTAGE: 6.3V; fp_ECN: 0402 SERIES_LL34.xls
R245 R284 = R: RES CHIP 5.1K 1/16W +-1%(0402); CLASS: DISCRETE; CMPLS_LVL: EP; Data: MAT_LF_RES SERIES.pdf; From_pj: S10-ANTONY; Lifecycle: Comp-Approve; MATERIAL: CHIP; Manuf_PN: RR0510S-512-FN; Manuf_name: CYNTEC CO.. LTD.; Manuftr: CYN; Not_insert: NI; Part_Type: *LF_Resistor; Status: Normal; TOLERANCE: 1%; WATTAGE: 1/16W; fp_ECN: 0402 SERIES_LL34.xls
R255 R262 = R: RES CHIP 5.1K 1/16W +-1%(0402); CLASS: DISCRETE; CMPLS_LVL: EP; Data: MAT_LF_RES SERIES.pdf; From_pj: S10-ANTONY; Lifecycle: Comp-Approve; MATERIAL: CHIP; Manuf_PN: RR0510S-512-FN; Manuf_name: CYNTEC CO.. LTD.; Manuftr: CYN; Part_Type: *LF_Resistor; Status: Normal; TOLERANCE: 1%; WATTAGE: 1/16W; fp_ECN: 0402 SERIES_LL34.xls
R390 = R: RES CHIP 22 1/16W +-1%(0402); CLASS: DISCRETE; CMPLS_LVL: EP; Data: RHT_LF_RES SERIES-2.pdf; From_pj: S75-L.A.; Lifecycle: Comp-Approve; MATERIAL: CHIP; Manuf_PN: CR0222R0F002S; Manuf_name: RTECH TECHNOLOGY CO..LTD. (Compostar); Manuftr: RHT; Not_insert: NI; Part_Type: *LF_Resistor; Standard: ##; Status: Preferred; TOLERANCE: 1%; WATTAGE: 1/16W; fp_ECN: 0402 SERIES_LL34.xls
R411 = R: RES CHIP 49.9 1/16W +-1% (0402); CLASS: DISCRETE; CMPLS_LVL: EP; Data: WTC_LF_WR SERIES.pdf; Lifecycle: Comp-Approve; MATERIAL: CHIP; Manuf_PN: RR0510S-49R9-FN; Manuf_name: CYNTEC CO.. LTD.; Manuftr: CYN; Not_insert: NI; Part_Type: *LF_Resistor; Status: Preferred; TOLERANCE: 1%; WATTAGE: 1/16W; fp_ECN: 0402 SERIES_LL34.xls
R832 R833 R861 R866-R871 R918-R925 = R: RES CHIP 0(1/20W,+-5%,0201); CLASS: DISCRETE; CMPLS_LVL: EP(V1); Data: YGO_RC0201JR-070RL.pdf; From_pj: F07-HENRY; Lifecycle: Comp-Approve; MATERIAL: CHIP; Manuf_PN: RC0201JR-130RL; Manuf_name: YAGEO CORPORATION; Manuftr: YGO; Not_insert: NI; Part_Type: *LF_Resistor; RD_CMPLS_LVL: EP(V1); TOLERANCE: 5%; WATTAGE: 1/20W; fp_ECN: DCN-ALL 0201 RCL PART.doc
R834 R835 = R: RES CHIP 5.1K 1/20W +-1%(0201); CLASS: DISCRETE; CMPLS_LVL: EP(V1); Data: YGO_LF_RES SERIES.pdf; From_pj: GD1-JACK; Lifecycle: Comp-Approve; MATERIAL: CHIP; Manuf_PN: RC0201FR-075K1L; Manuf_name: YAGEO CORPORATION; Manuftr: YGO; Part_Type: *LF_Resistor; RD_CMPLS_LVL: EP(V1); Standard: End of Design; TOLERANCE: 1%; WATTAGE: 1/20W; fp_ECN: DCN-all 0201 RCL part.doc
U48 U49 U65 U66 = 74AVCH1T45GM: IC OTHER(6P) 74AVCH1T45GM(XSON); CLASS: IC; CMPLS_LVL: EP(V1); Data: NXP_74AVCH1T45GM_REV4.pdf; From_pj: F07-HENRY; Lifecycle: Comp-Approve; MATERIAL: IC; Manuf_name: NXP semiconductors; Manuftr: NXP; Part_Type: *LF_Chipset; RD_CMPLS_LVL: EP(V1); Standard: Potential
C88 C89 C134 = CAP_NP: CAP CHIP 0.1U 16V(10%.X7R.0402); CLASS: DISCRETE; CMPLS_LVL: EP(V1); Data: MUR_LF_CAP SERIES_1.pdf; From_pj: S5A-TRAVIS; Lifecycle: Comp-Approve; MATERIAL: X7R; Manuf_PN: WBM155R71C104K; Manuf_name: MURATA ERIE N.A. INC TAIWAN BRANCH Okayama Murata Mfg.Co..Ltd. Wakura Murata Mfg; Manufacturer: AVX; Manuftr: MUR; Part_Type: *LF_C0402; RD_CMPLS_LVL: EP(V1); TOLERANCE: 10%; Top_Bot: BOT; VOLTAGE: 16V; fp_ECN: 0402 SERIES_LL34.xls
C147 = CAP_NP: CAP CHIP 0.1U 16V(10%.X7R.0402); CLASS: DISCRETE; CMPLS_LVL: EP(V1); Data: MUR_LF_CAP SERIES_1.pdf; From_pj: S5A-TRAVIS; Lifecycle: Comp-Approve; MATERIAL: X7R; Manuf_PN: WBM155R71C104K; Manuf_name: MURATA ERIE N.A. INC TAIWAN BRANCH Okayama Murata Mfg.Co..Ltd. Wakura Murata Mfg; Manufacturer: MUR; Manuftr: MUR; Part_Type: *LF_C0402; RD_CMPLS_LVL: EP(V1); TOLERANCE: 10%; VOLTAGE: 16V; fp_ECN: 0402 SERIES_LL34.xls; top_bot: TOP
C466 = CAP_NP: CAP CHIP 0.1U 25V(+-10%,X7R,0402); CLASS: DISCRETE; Data: YGO_CA-CC-SC SERIES.pdf; From_pj: F03-KC; Lifecycle: Comp-Approve; MATERIAL: X7R; Manuf_PN: CC0402KRX7R8BB104; Manuf_name: YAGEO CORPORATION; Manuftr: YGO; Part_Type: *LF_C0402; RD_CMPLS_LVL: EP(V1); Standard: End of Design; TOLERANCE: 10%; VOLTAGE: 25V; fp_ECN: 0402 SERIES_LL34.xls
R371 = R: RES CHIP 0.002 2W +-1%(2512); CLASS: DISCRETE; CMPLS_LVL: EP_Tmp; Data: WTC_WW25N_R2512_4P.pdf; EE_CHECK_LIST: R2512_4P.xls; FPLIST: R2512A,R2512_6P; From_pj: T96-JAMES; Lifecycle: Comp-Approve; MATERIAL: CHIP; Manuf_PN: WW25NR002FTL; Manuf_name: WALSIN TECHNOLOGY CORPORATION; Manuftr: WTC; Part_Type: *LF_Resistor; TOLERANCE: 1%; WATTAGE: 2W; fp_ECN: R2512A&4P&R2512_4PXF.doc
R374 R375 = R: RES CHIP 33.2 1/16W +-1%(0402); BOM: AST2300; CLASS: DISCRETE; CMPLS_LVL: EP; Data: CYN_LF_RL SERIES.pdf; From_pj: A06-EDISON; Lifecycle: Comp-Approve; MATERIAL: CHIP; Manuf_PN: RR0510S-33R2-FN; Manuf_name: CYNTEC CO.. LTD.; Manufacturer: CYN; Manuftr: CYN; Part_Type: *LF_Resistor; TOLERANCE: 1%; WATTAGE: 1/16W; fp_ECN: 0402 SERIES_LL34.xls; top_bot: TOP
R145 R380 R409 R1144 = R: RESISTOR CHIP 0 1/16W +-5%(0402); CLASS: DISCRETE; CMPLS_LVL: EP; Data: WTC_LF_WR SERIES.pdf; Lifecycle: Comp-Approve; MATERIAL: CHIP; Manuf_PN: RR0510X-000-XN; Manuf_name: CYNTEC CO.. LTD.; Manuftr: CYN; Part_Type: *LF_Resistor; Status: Preferred; TOLERANCE: 5%; WATTAGE: 1/16W; fp_ECN: 0402 SERIES_LL34.xls
R394 R973 R974 R997-R1002 = R: RES CHIP 1K 1/16W +-1% (0402); CLASS: DISCRETE; CMPLS_LVL: EP; Data: WTC_LF_WR SERIES.pdf; Lifecycle: Comp-Approve; MATERIAL: CHIP; Manuf_PN: RR0510S-102-FN; Manuf_name: CYNTEC CO.. LTD.; Manuftr: CYN; Part_Type: *LF_Resistor; Status: Preferred; TOLERANCE: 1%; WATTAGE: 1/16W; fp_ECN: 0402 SERIES_LL34.xls
R705 R729 = R: RES CHIP 10 1/16W +-1%(0402); CLASS: DISCRETE; CMPLS_LVL: EP; Data: TAI_LF_RM SERIES-3.pdf; From_pj: RS2-MATT; MATERIAL: CHIP; Manuf_PN: RM04FTN10R0; Manuf_name: TA-I TECHNOLOGY CO..LTD.; Manuftr: TAI; Part_Type: *LF_Resistor; TOLERANCE: 1%; WATTAGE: 1/16W; fp_ECN: 0402 SERIES_LL34.xls
U51 = INA230AIRGTR: IC OTHER (16P) INA230AIRGTR (QFN 3X3); CLASS: IC; CMPLS_LVL: EP(V1); Data: TIC_INA230_REV2012.pdf; From_pj: F07-HENRY; Lifecycle: Comp-Approve; MATERIAL: IC; Manuf_name: TEXAS INSTRUMENTS SUPPLY CO.,; Manuftr: TIC; Part_Type: *LF_Chipset; RD_CMPLS_LVL: EP(V1); Standard: Potential
C121 C122 = CAP_NP: CAP CHIP 0.1UF 16V(+-10%,X6S,0201); CLASS: DISCRETE; CMPLS_LVL: EP(V1); Data: TAY_EMK063AC6104KP.pdf; From_pj: S2P-SEAN; Lifecycle: Comp-Approve; MATERIAL: X6S; Manuf_PN: EMK063AC6104KP-F; Manuf_name: TAIYO YUDEN CO.,LTD; Manufacturer: MUR; Manuftr: TAY; Part_Type: *LF_C0201; RD_CMPLS_LVL: EP(V1); TOLERANCE: 10%; VOLTAGE: 16V; fp_ECN: DCN-all 0201 RCL part.doc
R320 = R: RES CHIP 4.7K 1/16W +-5% (0402); CLASS: DISCRETE; CMPLS_LVL: EP; Data: WTC_LF_WR SERIES.pdf; Lifecycle: Comp-Approve; MATERIAL: CHIP; Manuf_PN: RR0510S-472-JN; Manuf_name: CYNTEC CO.. LTD.; Manufacturer: RLC; Manuftr: CYN; Part_Type: *LF_Resistor; Status: Preferred; TOLERANCE: 5%; WATTAGE: 1/16W; fp_ECN: 0402 SERIES_LL34.xls; top_bot: TOP
R674 = R: RES CHIP 100K 1/16W +-1% (0402); BOM: AST2300; CLASS: DISCRETE; CMPLS_LVL: EP; Data: WTC_LF_WA06X SERIES.pdf; From_pj: S30-SP; Lifecycle: Comp-Approve; MATERIAL: CHIP; Manuf_PN: RR0510S-104-FN; Manuf_name: CYNTEC CO.. LTD.; Manufacturer: CYN; Manuftr: CYN; Not_insert: NI; Part_Type: *LF_Resistor; Status: Preferred; TOLERANCE: 1%; WATTAGE: 1/16W; fp_ECN: 0402 SERIES_LL34.xls
R704 = R: RES CHIP 0(1/20W,+-5%,0201); BOM: AST2300; CLASS: DISCRETE; CMPLS_LVL: EP(V1); Data: YGO_RC0201JR-070RL.pdf; From_pj: F07-HENRY; Lifecycle: Comp-Approve; MATERIAL: CHIP; Manuf_PN: RC0201JR-130RL; Manuf_name: YAGEO CORPORATION; Manufacturer: CYN; Manuftr: YGO; Part_Type: *LF_Resistor; RD_CMPLS_LVL: EP(V1); TOLERANCE: 5%; WATTAGE: 1/20W; fp_ECN: DCN-ALL 0201 RCL PART.doc; top_bot: TOP
R984-R987 = R: RES CHIP 3.3K 1/16W +-1%(0402); CLASS: DISCRETE; CMPLS_LVL: EP; Data: TAI_LF_RM SERIES-2.pdf; From_pj: S75-LA; Lifecycle: Comp-Approve; MATERIAL: CHIP; Manuf_PN: RM04FTN3301; Manuf_name: TA-I TECHNOLOGY CO..LTD.; Manuftr: TAI; Part_Type: *LF_Resistor; Standard: ##; Status: Preferred; TOLERANCE: 1%; WATTAGE: 1/16W; fp_ECN: 0402 SERIES_LL34.xls
R144 R1004 R1009-R1013 R1344-R1346 = R: RES CHIP 10K 1/16W +-1% (0402); CLASS: DISCRETE; CMPLS_LVL: EP; Data: WTC_LF_WR SERIES.pdf; From_pj: S82; Lifecycle: Comp-Approve; MATERIAL: CHIP; Manuf_PN: RR0510S-103-FN; Manuf_name: CYNTEC CO.. LTD.; Manuftr: CYN; Part_Type: *LF_Resistor; Status: Preferred; TOLERANCE: 1%; WATTAGE: 1/16W; fp_ECN: 0402 SERIES_LL34.xls
R1411-R1413 = R: RES CHIP 4.7K 1/16W +-5% (0402); BOM: TI; CLASS: DISCRETE; CMPLS_LVL: EP; Data: WTC_LF_WR SERIES.pdf; Lifecycle: Comp-Approve; MATERIAL: CHIP; Manuf_PN: RR0510S-472-JN; Manuf_name: CYNTEC CO.. LTD.; Manuftr: CYN; Not_insert: NI; Part_Type: *LF_Resistor; Status: Preferred; TOLERANCE: 5%; WATTAGE: 1/16W; fp_ECN: 0402 SERIES_LL34.xls
U81 = WGI210ATQPVTA1: IC CTRL(64P) WGI210AT-SLJXR A2(QFN); CLASS: IC; CMPLS_LVL: SEA; Data: SPRINGVILLE GBE CONTROLLER_REV1-7-2.pdf; From_pj: S1D-OZ; Lifecycle: Comp-Approve; MATERIAL: IC; Manuf_name: INTEL SEMICONDUCTOR LTD.; Manuftr: INT; Part_Type: *LF_Chipset; RD_CMPLS_LVL: EP(V1); Standard: Potential
C545 = CAP_NP: CAP CHIP 0.1U 16V(10%.X7R.0402); CLASS: DISCRETE; CMPLS_LVL: EP(V1); Data: MUR_LF_CAP SERIES_1.pdf; From_pj: S5A-TRAVIS; Lifecycle: Comp-Approve; MATERIAL: X7R; Manuf_PN: WBM155R71C104K; Manuf_name: MURATA ERIE N.A. INC TAIWAN BRANCH Okayama Murata Mfg.Co..Ltd. Wakura Murata Mfg; Manufacturer: MUR; Manuftr: MUR; Part_Type: *LF_C0402; RD_CMPLS_LVL: EP(V1); ROOM: VR_P1V05_PCH; TOLERANCE: 10%; Top_bot: TOP; VOLTAGE: 16V; fp_ECN: 0402 SERIES_LL34.xls
C546-C550 C554-C558 C561-C565 = CAP_NP: CAP CHIP 0.1U 16V(10%.X7R.0402); CLASS: DISCRETE; CMPLS_LVL: EP(V1); Data: MUR_LF_CAP SERIES_1.pdf; From_pj: S5A-TRAVIS; Lifecycle: Comp-Approve; MATERIAL: X7R; Manuf_PN: WBM155R71C104K; Manuf_name: MURATA ERIE N.A. INC TAIWAN BRANCH Okayama Murata Mfg.Co..Ltd. Wakura Murata Mfg; Manuftr: MUR; Part_Type: *LF_C0402; RD_CMPLS_LVL: EP(V1); TOLERANCE: 10%; VOLTAGE: 16V; fp_ECN: 0402 SERIES_LL34.xls
C551 = CAP_NP: CAP CHIP 47U 6.3V(+-20%.X5R.0805); CLASS: DISCRETE; CMPLS_LVL: EP(V1); Data: XMK-series.pdf; From_pj: LB8D-JERRY; Lifecycle: Comp-Approve; MATERIAL: X5R; Manuf_PN: JMK212BJ476MG-T; Manuf_name: TAIYO YUDEN CO..LTD; Manuftr: TAY; Part_Type: *LF_C0805; RD_CMPLS_LVL: EP(V1); TOLERANCE: 20%; VOLTAGE: 6.3V
C552 C559 C566 = CAP_NP: CAP CHIP 10UF 16V(+-10%,X7R,0805); CLASS: DISCRETE; CMPLS_LVL: EP(V1); Data: SAM_MLCC SERIES_20130308.pdf; From_pj: T2H-CHEESE; Lifecycle: Comp-Approve; MATERIAL: X7R; Manuf_PN: CL21B106KOQNNNE; Manuf_name: SAMSUNG ELECTRONICS CO.,LTD; Manuftr: SAM; Part_Type: *LF_C0805; RD_CMPLS_LVL: EP(V1); TOLERANCE: 10%; VOLTAGE: 16V
C553 = CAP_NP: CAP CHIP 0.039U 16V(+-10%.X7R.0603); CLASS: DISCRETE; CMPLS_LVL: EP; Data: TDK_C Series.pdf; From_pj: T69; Lifecycle: Comp-Approve; MATERIAL: X7R; Manuf_PN: 2238 786 15644; Manuf_name: PHYCOMP TAIWAN LTD.(YAGEO); Manuftr: PHY; Part_Type: *LF_C0603; Status: Normal; TOLERANCE: 10%; VOLTAGE: 16V
C560 C567 = CAP_NP: CAP CHIP 22U 16V(+-20%,X6S,0805); CLASS: DISCRETE; Data: MUR_GRM21BC81C226ME44L.pdf; From_pj: F08-ATLUS; Lifecycle: Comp-Approve; MATERIAL: X6S; Manuf_PN: GRM21BC81C226M; Manuf_name: MURATA ERIE N.A. INC TAIWAN BRANCH Okayama Murata Mfg.Co.,Ltd.Wakura Murata Mfg.; Manuftr: MUR; Part_Type: *LF_C0805; RD_CMPLS_LVL: EP(V1); TOLERANCE: 20%; VOLTAGE: 16V
C609 C610 = CAP_NP: CAP CHIP 30P 50V(+-5% NPO 0402); CLASS: DISCRETE; CMPLS_LVL: EP; Data: TDK_C Series_1.pdf; From_pj: S65-JOSEPH; Lifecycle: Comp-Approve; MATERIAL: NPO; Manuf_PN: C1005C0G1H300J-B; Manuf_name: TDK TAIWAN CORP.TDK XIAMEN CO..LTD; Manuftr: TDK; Part_Type: *LF_C0402; TOLERANCE: 5%; VOLTAGE: 50V; fp_ECN: 0402 SERIES_LL34.xls
R975 = R: RES CHIP 27K 1/16W +-5%(0402); CLASS: DISCRETE; CMPLS_LVL: EP; Data: WTC_LF_WR SERIES-4.pdf; From_pj: S50-STRVE; Lifecycle: Comp-Approve; MATERIAL: CHIP; Manuf_PN: WR04X273 JTL; Manuf_name: WALSIN TECHNOLOGY CORPORATION; Manuftr: WTC; Part_Type: *LF_Resistor; TOLERANCE: 5%; WATTAGE: 1/16W; fp_ECN: 0402 SERIES_LL34.xls
R991-R993 = R: RESISTOR CHIP 0 1/10W+-5%(0603); CLASS: DISCRETE; CMPLS_LVL: EP; Data: WTC_LF_WR SERIES.pdf; Lifecycle: Comp-Approve; MATERIAL: CHIP; Manuf_PN: CRCW06030000Z0EA; Manuf_name: DALE ELECTRONICS.INC.; Manuftr: DAL; Part_Type: *LF_Resistor; Standard: ##; Status: Normal; TOLERANCE: 5%; WATTAGE: 1/10W
R1003 = R: RES CHIP 4.99K 1/16W +-1% (0402); CLASS: DISCRETE; CMPLS_LVL: EP; Data: RHT_LF_RES SERIES-3.pdf; From_pj: JS1-JACK; Lifecycle: Comp-Approve; MATERIAL: CHIP; Manuf_PN: RR0510S-4991-FN; Manuf_name: CYNTEC CO.. LTD.; Manuftr: CYN; Part_Type: *LF_Resistor; Status: Preferred; TOLERANCE: 1%; WATTAGE: 1/16W; fp_ECN: 0402 SERIES_LL34.xls
R1143 = R: RES CHIP 1M 1/16W +-1% (0402); CLASS: DISCRETE; CMPLS_LVL: EP; Data: TAI_LF_RM SERIES-3.pdf; From_pj: LU1-EASON; Lifecycle: Comp-Approve; MATERIAL: CHIP; Manuf_PN: RM04FTN1004; Manuf_name: TA-I TECHNOLOGY CO..LTD.; Manuftr: TAI; Part_Type: *LF_Resistor; TOLERANCE: 1%; WATTAGE: 1/16W; fp_ECN: 0402 SERIES_LL34.xls
U82 = M25PE16VMW6TP: IC FLASH(8P) M25PE16-VMW6TP(SO8W); CLASS: IC; CMPLS_LVL: EP_Tmp; Data: SGT_M25PE16.pdf; EE_CHECK_LIST: SOIC8_6-22_H99.xls; From_pj: TU1-TOD; Lifecycle: Comp-Approve; MATERIAL: IC; Manuf_name: SGS-THOMSON(STMicroelectronics); Manuftr: SGT; Part_Type: *LF_Chipset; Standard: Potential
Y4 = X_4S_CX3225SB25000D0FPLCC: XTAL SMD 25MHZ(10PPM,18PF)8Z25000020; CLASS: IO; Data: TXC_8Z25000020.pdf; From_pj: F09-TONY; Lifecycle: P/N Release; MATERIAL: MISC; Manuf_PN: 8Z25000020; Manuf_name: TAIWAN X'TAL CORPATION (TXC Corporation); Manuftr: TXC; Part_Type: *LF_Misc; RD_CMPLS_LVL: EP(V1); Standard: Potential
DM1 = DUMMY_SYMBOL: CE LOGO_5.842X5.08; CLASS: IO; Data: Safety EMC logo.xlsx; From_pj: T6MG-RAYMOND; MATERIAL: MECH; Part_Type: Mech
DM2 DM5 DM7 = DUMMY_SYMBOL: CLASS: IO; MATERIAL: MECH; Part_Type: Mech
DM3 = ME_DUMMY_SYMBOL: From_pj: XG1-TONY; MATERIAL: MECH; Part_Type: Mech
H7-H10 = HOLE: CLASS: IO; DIP_SMD: DIP; From_pj: SN7; MATERIAL: MECH; Part_Type: Mech
H16-H20 = GND_HOLE: CLASS: IO; DIP_SMD: DIP; From_pj: S1U-TORRES; MATERIAL: MECH; Part_Type: Mech
H21 H22 = HOLE_N: CLASS: IO; DIP_SMD: DIP; Data: HOLE_TOOLINGD125N_T2-0.msg; MATERIAL: MECH; Part_Type: Mech
ME1-ME8 = ME_DUMMY_SYMBOL: MATERIAL: MECH; Part_Type: Mech
TP_BIOS_LABEL = TP: TEST POINT (TP26D10) DIP(DRILL10MILS); ALT_SYMBOLS: TOP:TP26D10;BOTTOM:TP30D10; CLASS: IO; Cost: Others; DIP_SMD: DIP; From_pj: S56; MATERIAL: MISC; Part_Type: Misc; SUBSYS: FWH_RES; TOP_BOT: TOP
C82 = CAP_NP: CAP CHIP 100NF 50V(+-10%,X7R,0402); CLASS: DISCRETE; CMPLS_LVL: EP(V1); Data: YGO_CLASS-2-X7R_REV9.pdf; From_pj: S1M-JHIH-RONG; Lifecycle: Comp-Release Qty; MATERIAL: X7R; Manuf_PN: CC0402KRX7R9BB104; Manuf_name: YAGEO CORPORATION; Manufacturer: AVX; Manuftr: YGO; Not_insert: NI; Part_Type: *LF_C0402; RD_CMPLS_LVL: EP(V1); Standard: End of Design; TOLERANCE: 10%; Top_Bot: BOT; VOLTAGE: 50V; fp_ECN: 0402 SERIES_LL34.xls
C95 = CAP_NP: CAP CHIP 0.1U 25V(+-10%,X7R,0402); CLASS: DISCRETE; Data: YGO_CA-CC-SC SERIES.pdf; From_pj: F03-KC; Lifecycle: Comp-Approve; MATERIAL: X7R; Manuf_PN: CC0402KRX7R8BB104; Manuf_name: YAGEO CORPORATION; Manuftr: YGO; Part_Type: *LF_C0402; RD_CMPLS_LVL: EP(V1); Standard: End of Design; TOLERANCE: 10%; TOP_BOT: TOP; VOLTAGE: 25V; fp_ECN: 0402 SERIES_LL34.xls
R172 = R: RES CHIP 10K 1/16W +-1% (0402); CLASS: DISCRETE; CMPLS_LVL: EP; Data: WTC_LF_WR SERIES.pdf; From_pj: S82; Lifecycle: Comp-Approve; MATERIAL: CHIP; Manuf_PN: RR0510S-103-FN; Manuf_name: CYNTEC CO.. LTD.; Manuftr: CYN; Not_insert: NI; Part_Type: *LF_Resistor; Status: Preferred; TOLERANCE: 1%; WATTAGE: 1/16W; fp_ECN: 0402 SERIES_LL34.xls
U23 = BSZ017NE2LS5I: TRANS MOS BSZ017NE2LS5I(25V,40A,50W); CLASS: IC; Data: SNI_BSZ017NE2LS5I.pdf; From_pj: T2N-HSUEH-YEN; Lifecycle: P/N Release; MATERIAL: IC; Manuf_name: INFINEON TECHNOLOGIES ASIA PACIFIC; Manuftr: SNI; Part_Type: *LF_Semiconductor; RD_CMPLS_LVL: EP(V1); Standard: Non-Preferred
U26 = SLG55021131010V: IC OTHER(8P) SLG55021-200010VTR(TDFN-8); CLASS: IC; Data: SLG55021-200010Vr062.pdf; From_pj: S81K-STANLEY; Lifecycle: Comp-Approve; MATERIAL: IC; Manuf_name: SILEGO TECHNOLOGY INC.; Manuftr: SLG; Part_Type: *LF_Chipset; RD_CMPLS_LVL: EP(V1); Standard: ##; TOP_BOT: TOP
R872-R907 R926-R952 = R: RESISTOR CHIP 0 1/16W +-5%(0402); CLASS: DISCRETE; CMPLS_LVL: EP; Data: WTC_LF_WR SERIES.pdf; Lifecycle: Comp-Approve; MATERIAL: CHIP; Manuf_PN: RR0510X-000-XN; Manuf_name: CYNTEC CO.. LTD.; Manuftr: CYN; Not_insert: NI; Part_Type: *LF_Resistor; Status: Preferred; TOLERANCE: 5%; WATTAGE: 1/16W; fp_ECN: 0402 SERIES_LL34.xls
R908 R953-R961 = R: RESISTOR CHIP 0 1/10W+-5%(0603); CLASS: DISCRETE; CMPLS_LVL: EP; Data: WTC_LF_WR SERIES.pdf; Lifecycle: Comp-Approve; MATERIAL: CHIP; Manuf_PN: CRCW06030000Z0EA; Manuf_name: DALE ELECTRONICS.INC.; Manufacturer: CYN; Manuftr: DAL; Not_insert: NI; Part_Type: *LF_Resistor; Standard: ##; Status: Normal; TOLERANCE: 5%; WATTAGE: 1/10W
R909-R914 R962-R965 = R: RESISTOR CHIP 0 1/8W +-5%(0805); CLASS: DISCRETE; CMPLS_LVL: EP; Data: WTC_LF_WR SERIES.pdf; Lifecycle: Comp-Approve; MATERIAL: CHIP; Manuf_PN: ERJ6GEY0R00V; Manuf_name: MATSUSHITA ELECTRONICS CORPORATION (PANASONIC)Wuxi Matsushita Battery Co.. Ltd; Manuftr: MAT; Not_insert: NI; Part_Type: *LF_Resistor; Standard: ##; Status: Normal; TOLERANCE: 5%; WATTAGE: 1/8W
R915-R917 R966 R967 = R: RES CHIP 0 1/4W +-5%(1206); CLASS: DISCRETE; CMPLS_LVL: EP; Data: RHT_LF_RES SERIES.pdf; Lifecycle: Comp-Release Qty; MATERIAL: CHIP; Manuf_PN: ERJ8GEY0R00V; Manuf_name: MATSUSHITA ELECTRONICS CORPORATION (PANASONIC)Wuxi Matsushita Battery Co.. Ltd; Manuftr: MAT; Not_insert: NI; Part_Type: *LF_Resistor; Status: Normal; TOLERANCE: 5%; WATTAGE: 1/4W

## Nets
14.3V_VR_P1V05_PROC_IO_G: C82.1 R145.2 U23.4(G)
14.3V_VR_P1V05_PROC_IO_G_R: R145.1 U26.7(G)
GND: C82.2 C88.2 C89.2 C95.2 C132.2 C133.2 C134.2 C135.2 C147.1 C148.2 C545.2 C546.2 C547.2 C548.2 C549.2 C550.2 C551.2 C552.2 C554.2 C555.2 C556.2 C557.2 C558.2 C559.2 C560.2 C561.2 C562.2 C563.2 C564.2 C565.2 C566.2 C567.2 C609.2 C610.2 C636.2 C641.2 C707.2 C708.2 H7.1(GND) H8.1(GND) H9.1(GND) H10.1(GND) H16.2(GND2) H16.3(GND3) H16.4(GND4) H16.5(GND5) H16.6(GND6) H16.7(GND7) H16.8(GND8) H16.9(GND9) H17.2(GND2) H17.3(GND3) H17.4(GND4) H17.5(GND5) H17.6(GND6) H17.7(GND7) H17.8(GND8) H17.9(GND9) H18.2(GND2) H18.3(GND3) H18.4(GND4) H18.5(GND5) H18.6(GND6) H18.7(GND7) H18.8(GND8) H18.9(GND9) H19.2(GND2) H19.3(GND3) H19.4(GND4) H19.5(GND5) H19.6(GND6) H19.7(GND7) H19.8(GND8) H19.9(GND9) H20.2(GND2) H20.3(GND3) H20.4(GND4) H20.5(GND5) H20.6(GND6) H20.7(GND7) H20.8(GND8) H20.9(GND9) R245.2 R284.2 R380.2 R409.2 R674.1 R1003.1 R1235.2 R1344.1 R1345.1 R1346.1 U26.4(GND) U26.TH U48.2(GND) U49.2(GND) U50.3(GND) U51.10(GND) U51.TH U65.2(GND) U66.2(GND) U81.TH(E_PAD_GND) U82.4(VSS) U101.3(GND) U105.3(GND) U121.3(GND) U122.3(GND) Y4.2(G1) Y4.4(G2) ; also on sheet 1 2 3 4 11 12 13 14 15 16 17 18 19 20 22 23 24 25 26 27 28 31 32 41 42 45 46 47 48 49 50 51 52 53 54 55 56 57 58 59 60 61 62 63 64 65 66 67 68 69 70 71 72 73 74 75 77 79 81
P0V9_AUX_LAN1: C554.1 C555.1 C556.1 C557.1 C558.1 C559.1 C560.1 R993.2 U81.11(VDD0P9) U81.32(VDD0P9) U81.42(VDD0P9) U81.59(VDD0P9)
P0V9_AUX_LAN1_R: R993.1 U81.38(VDD0P9_OUT)
P1V5_AUX_LAN1: C561.1 C562.1 C563.1 C564.1 C565.1 C566.1 C567.1 R992.2 U81.47(VDD1P5) U81.56(VDD1P5)
P1V5_AUX_LAN1_R: R992.1 U81.39(VDD1P5_OUT)
P1V05_COMBINED: C89.1 C132.1 C133.1 R255.1 R262.1 R834.1 R835.1 U23.5_8(D) U26.5(D) U48.1(VCC_A) U48.5(DIR) U49.1(VCC_A) U49.5(DIR) U65.1(VCC_A) U66.1(VCC_A) ; also on sheet 1 3 4 16 18 19 41 42 45 47 48 50 51 52 54 55 56 63 71 74 75 79 94
P1V05_PCH: C88.1 U23.1_3(S) U26.6(S) ; also on sheet 50 51 52 63 67 74
P3V3_STBY: C134.1 C135.1 C147.2 C148.1 C545.1 C546.1 C547.1 C548.1 C549.1 C550.1 C551.1 C552.1 C636.1 C641.1 C707.1 C708.1 R144.2 R172.2 R320.1 R363.1 R394.1 R973.1 R974.1 R975.1 R984.1 R985.1 R986.1 R987.1 R991.1 R997.1 R998.1 R999.1 R1000.1 R1001.1 R1002.1 R1004.1 R1009.1 R1010.1 R1011.1 R1012.1 R1013.1 R1195.1 R1196.1 R1234.2 R1254.2 R1255.2 R1260.2 R1411.2 R1412.2 R1413.2 U48.6(VCC_B) U49.6(VCC_B) U50.5(VCC) U51.9(VS) U65.6(VCC_B) U66.6(VCC_B) U81.10(VDD3P3) U81.27(VDD3P3) U81.41(VDD3P3) U81.64(VDD3P3) U82.8(VCC) U101.5(VCC) U105.5(VCC) U121.5(VCC) U122.5(VCC) ; also on sheet 3 4 13 14 16 18 19 20 22 24 25 26 27 28 31 32 41 52 55 56 57 58 59 62 63 64 65 67 68 69 70 71 72 73 74 75 77 79 81
P3V3_STBY_LAN1_R: R991.2 U81.51(VDD3P3)
P5V_STBY: C95.1 U26.1(VCC) U26.3(SHDN#) ; also on sheet 1 2 13 23 26 31 70 74
P12V_STBY: R371.1 R705.1 ; also on sheet 2 3 23 24 25 27 28 74
P12V_STBY_CONN: R371.2 R729.1 U51.11(BUS) ; also on sheet 12 13
BIOS_DIS0_BUF_N: R1231.2 ; also on sheet 59
BIOS_DIS0_BUF_R_N: R1231.1 U101.4(Y)
BIOS_DIS0_N: R1234.1 R1235.1 U101.2(A) ; also on sheet 65
CARRIER_BOARD_PWR_OK: U121.1(OE) U122.1(OE) ; also on sheet 65
CLK_100M_I210_DN: U81.25(PE_CLKN) ; also on sheet 49
CLK_100M_I210_DP: U81.26(PE_CLKP) ; also on sheet 49
FM_CPLD_P1V05_PCH_EN: R172.1 U26.2(ON) ; also on sheet 14
I210_CBOT: C553.2 U81.37(CBOT)
I210_CTOP: C553.1 U81.40(CTOP)
I210_IRQ_ALERT_N: R990.2 U81.35(SMB_ALRT_N)
LAN_I210_MDI0_N: U81.57(MDI_0_N) ; also on sheet 65
LAN_I210_MDI0_P: U81.58(MDI_0_P) ; also on sheet 65
LAN_I210_MDI1_N: U81.54(MDI_1_N) ; also on sheet 65
LAN_I210_MDI1_P: U81.55(MDI_1_P) ; also on sheet 65
LAN_I210_MDI2_N: U81.52(MDI_2_N) ; also on sheet 65
LAN_I210_MDI2_P: U81.53(MDI_2_P) ; also on sheet 65
LAN_I210_MDI3_N: U81.49(MDI_3_N) ; also on sheet 65
LAN_I210_MDI3_P: U81.50(MDI_3_P) ; also on sheet 65
LAN_MDC0_LVC3_GF: R390.2 U49.4(B) ; also on sheet 12
LAN_MDC1_GBE: U48.3(A) ; also on sheet 45
LAN_MDC1_LVC3_GF: U48.4(B) ; also on sheet 12
LAN_MDIO0_DIR_GBE: R255.2 R284.1 R832.1 ; also on sheet 45
LAN_MDIO0_DIR_GBE_R: R832.2 R835.2 U65.5(DIR)
LAN_MDIO0_LVC3_GF: R411.2 U65.4(B) ; also on sheet 12
LAN_MDIO1_DIR_GBE: R245.1 R262.2 R833.1 ; also on sheet 45
LAN_MDIO1_DIR_GBE_R: R833.2 R834.2 U66.5(DIR)
LAN_MDIO1_GBE: U66.3(A) ; also on sheet 45
LAN_MDIO1_LVC3_GF: U66.4(B) ; also on sheet 12
LED0_LAN_MDC0_SPEED_1: U49.3(A) ; also on sheet 45
LED0_LAN_MDIO0_STAT_ACTVT_0: U65.3(A) ; also on sheet 45
LED0_LAN_SPEED: R390.1 ; also on sheet 71
LED0_NIC_LINK_ACT_N: R411.1 ; also on sheet 71
LED_I210_LED0_N: R1411.1 U81.31(LED0) ; also on sheet 65
LED_I210_LED1_N: R1412.1 U81.30(LED1) ; also on sheet 65
LED_I210_LED2_N: R1413.1 U81.33(LED2) ; also on sheet 65
NIC1_DEV_OFF_R_N: R1002.2 U81.28(DEV_OFF_N)
NIC1_PCIE_OFF_N: R985.2 U81.61(SDP1|_PCIE_DIS)
P2E_PCH_I210_RX_DN: C122.1 ; also on sheet 94
P2E_PCH_I210_RX_DN_C: C122.2 U81.20(PE_TN)
P2E_PCH_I210_RX_DP: C121.1 ; also on sheet 94
P2E_PCH_I210_RX_DP_C: C121.2 U81.21(PE_TP)
P2E_PCH_I210_TX_DN: U81.23(PE_RN) ; also on sheet 94
P2E_PCH_I210_TX_DP: U81.24(PE_RP) ; also on sheet 94
PD_CLK_50M_NIC1: R1344.2 U81.2(NC_SI_CLK_IN)
PD_INA230_A0: R380.1 U51.2(A0)
PD_INA230_A1: R409.1 U51.1(A1)
PD_RMII_NIC1_CRS_DV: R1345.2 U81.3(NC_SI_CRS_DV)
PD_RMII_NIC1_TX_EN_R: R1346.2 U81.7(NC_SI_TX_EN)
PD_RSET_NIC1: R1003.2 U81.48(RSET)
PU_NIC1_AUXPWR_TCK: R997.2 U81.19(JTAG_CLK)
PU_NIC1_EEPROM_TMS: R999.2 U81.18(JTAG_TMS)
PU_NIC1_LAN_PWR_GOOD: R1001.2 U81.1(LAN_PWR_GOOD)
PU_NIC1_SDP0: R984.2 U81.63(SDP0)
PU_NIC1_SDP2: R986.2 U81.62(SDP2)
PU_NIC1_SDP3: R987.2 U81.60(SDP3)
PU_NIC1_TDI: R998.2 U81.29(JTAG_TDI)
PU_NIC1_TDO: R1000.2 U81.4(JTAG_TDO)
PU_RMII_NIC1_RXD_0_R: R1010.2 U81.6(NC_SI_RXD0)
PU_RMII_NIC1_RXD_1_R: R1011.2 U81.5(NC_SI_RXD1)
PU_RMII_NIC1_TXD_0_R: R1004.2 U81.9(NC_SI_TXD0)
PU_RMII_NIC1_TXD_1_R: R1009.2 U81.8(NC_SI_TXD1)
PU_SPI_NIC1_HLD_N: R974.2 U82.7(RESET#)
PU_SPI_NIC1_WP_N: R973.2 U82.3(W#)
PWR_BTN_COME_BUF_N: U121.4(Y) ; also on sheet 69
PWR_BTN_COME_N: R1254.1 U121.2(A) ; also on sheet 65
PWRGD_P1V05_PCH: R1163.2 ; also on sheet 64
PWRGD_P1V05_PCH_R: R144.1 R1163.1 U26.8(PG)
RMII_NIC1_SI_ARB_IN: R1012.2 U81.43(NC_SI_ARB_IN)
RMII_NIC1_SI_ARB_OUT: R1013.2 U81.44(NC_SI_ARB_OUT)
RST_BTN_COME_BUF_N: U122.4(Y) ; also on sheet 69
RST_BTN_COME_N: R1255.1 U122.2(A) ; also on sheet 13
RST_PLTRST_I210_N: R704.1 ; also on sheet 58
RST_PLTRST_I210_N_R: R674.2 R704.2 U81.17(PE_RST_N)
SLP_SUS_STAT_BUF_N: R1259.2 R1260.1 ; also on sheet 65
SLP_SUS_STAT_BUF_R_N: R1259.1 U105.4(Y)
SLP_SUS_STAT_N: U105.2(A) ; also on sheet 63 71
SMB_INA230_ALRT_N: R1351.2 ; also on sheet 47
SMB_INA230_ALRT_N_PROCHOT: R1350.2 U50.2(A) ; also on sheet 64 71
SMB_INA230_ALRT_N_PROCHOT_R: R363.2 R1350.1 U51.3(ALERT)
SMB_INA230_ALRT_N_R: R394.2 R1351.1 U50.4(Y)
SMB_INA230_SCL_R: R374.1 R1195.2 U51.5(SCL)
SMB_INA230_SDA_R: R375.1 R1196.2 U51.4(SDA)
SMB_LAN_3V3SB_ALRT_N: R990.1 ; also on sheet 75
SMB_LAN_3V3SB_CLK: R988.1 ; also on sheet 75
SMB_LAN_3V3SB_DAT: R989.1 ; also on sheet 75
SMB_LAN_3V3STBY_CLK_R: R988.2 U81.34(SMB_CLK)
SMB_LAN_3V3STBY_DAT_R: R989.2 U81.36(SMB_DATA)
SMB_SML1_3V3SB_CLK: R374.2 ; also on sheet 18
SMB_SML1_3V3SB_DAT: R375.2 ; also on sheet 18
SPI_NIC1_CS_N: R971.2 U82.1(S#)
SPI_NIC1_CS_R_N: R971.1 U81.15(NVM_CS_N)
SPI_NIC1_NVM_SO: R968.2 U81.14(NVM_SO)
SPI_NIC1_NVM_SO_R: R968.1 U82.2(DQ1)
SPI_NIC1_SI: R969.2 R975.2 U82.5(DQ0)
SPI_NIC1_SI_R: R969.1 U81.12(NVM_SI)
SPI_NIC1_SK: R970.2 U82.6(C)
SPI_NIC1_SK_R: R970.1 U81.13(NVM_SK)
TP_C17_1: R910.2
TP_C60_1: R911.2
TP_C62_1: R912.2
TP_C65_1: R876.2
TP_C70_1: R877.2
TP_C92_1: R878.2
TP_C93_1: R879.2
TP_C102_1: R872.2
TP_C111_1: R909.2
TP_C115_1: R873.2
TP_C119_1: R874.2
TP_C170_1: R861.1
TP_C177_1: R866.1
TP_C179_1: R867.1
TP_C197_1: R868.1
TP_C199_1: R869.1
TP_C210_1: R918.1
TP_C240_1: R875.2
TP_C253_1: R953.1
TP_C258_1: R926.2
TP_C259_1: R927.2
TP_C289_1: R928.2
TP_C312_1: R954.1
TP_C329_1: R955.1
TP_C343_1: R956.1
TP_C381_1: R929.2
TP_C384_1: R930.2
TP_C396_1: R919.1
TP_C420_1: R931.2
TP_C421_1: R932.2
TP_C422_1: R920.1
TP_C449_1: R933.2
TP_C456_1: R966.2
TP_C472_1: R957.1
TP_C484_1: R962.2
TP_C488_1: R921.1
TP_C494_1: R922.1
TP_C520_1: R915.2
TP_C529_1: R908.1
TP_ICT_BOT: R918.2 R919.2 R920.2 R921.2 R922.2 R923.2 R924.2 R925.2 R926.1 R927.1 R928.1 R929.1 R930.1 R931.1 R932.1 R933.1 R934.1 R935.1 R936.1 R937.1 R938.1 R939.1 R940.1 R941.1 R942.1 R943.1 R944.1 R945.1 R946.1 R947.1 R948.1 R949.1 R950.1 R951.1 R952.1 R953.2 R954.2 R955.2 R956.2 R957.2 R958.2 R959.2 R960.2 R961.2 R962.1 R963.1 R964.1 R965.1 R966.1 R967.1
TP_ICT_TOP: R861.2 R866.2 R867.2 R868.2 R869.2 R870.2 R871.2 R872.1 R873.1 R874.1 R875.1 R876.1 R877.1 R878.1 R879.1 R880.1 R881.1 R882.1 R883.1 R884.1 R885.1 R886.1 R887.1 R888.1 R889.1 R890.1 R891.1 R892.1 R893.1 R894.1 R895.1 R896.1 R897.1 R898.1 R899.1 R900.1 R901.1 R902.1 R903.1 R904.1 R905.1 R906.1 R907.1 R908.2 R909.1 R910.1 R911.1 R912.1 R913.1 R914.1 R915.1 R916.1 R917.1
TP_PC2_1: R916.2
TP_PC10_1: R880.2
TP_PC17_1: R913.2
TP_PC21_1: R881.2
TP_PC72_1: R882.2
TP_PC77_1: R917.2
TP_PC81_1: R967.2
TP_PC86_1: R965.2
TP_PC101_1: R935.2
TP_PC116_1: R963.2
TP_PC122_1: R964.2
TP_PR1_1: R883.2
TP_PR9_1: R892.2
TP_PR10_1: R884.2
TP_PR11_1: R885.2
TP_PR18_1: R886.2
TP_PR19_1: R887.2
TP_PR32_1: R888.2
TP_PR35_1: R889.2
TP_PR36_1: R890.2
TP_PR63_1: R891.2
TP_PR67_1: R940.2
TP_PR68_1: R959.1
TP_PR73_1: R939.2
TP_PR76_1: R941.2
TP_PR95_1: R960.1
TP_PR96_1: R942.2
TP_PR102_1: R934.2
TP_PR104_1: R936.2
TP_PR106_1: R938.2
TP_PR107_1: R937.2
TP_PR108_1: R958.1
TP_R4_1: R905.2
TP_R13_1: R943.2
TP_R38_1: R904.2
TP_R40_1: R871.1
TP_R65_1: R906.2
TP_R114_1: R893.2
TP_R168_1: R894.2
TP_R178_1: R895.2
TP_R190_1: R897.2
TP_R202_1: R896.2
TP_R204_1: R898.2
TP_R227_1: R900.2
TP_R275_1: R899.2
TP_R286_1: R902.2
TP_R351_1: R901.2
TP_R369_1: R870.1
TP_R378_1: R903.2
TP_R450_1: R944.2
TP_R461_1: R946.2
TP_R500_1: R923.1
TP_R517_1: R961.1
TP_R575_1: R945.2
TP_R587_1: R947.2
TP_R617_1: R948.2
TP_R626_1: R949.2
TP_R661_1: R924.1
TP_R748_1: R950.2
TP_R774_1: R951.2
TP_R780_1: R952.2
TP_R834_1: R925.1
TP_R849_1: R907.2
TP_R860_1: R914.2
VSENSE_P12V_INA230_INN: C466.2 R705.2 U51.12(IN-)
VSENSE_P12V_INA230_INP: C466.1 R729.2 U51.13(IN+)
WAKE_R1_N: R320.2 U81.16(PE_WAKE_N)
XTAL_1_25M_NIC1: R1144.2 U81.46(XTAL1)
XTAL_1_25M_NIC1_R: C609.1 R1143.1 R1144.1 Y4.1(X1)
XTAL_2_25M_NIC1: C610.1 R1143.2 U81.45(XTAL2) Y4.3(X2)

Not connected (* = marked no-connect by the designer): DM1 1; DM2 1; DM5 1; DM7 1; H21 1(GND)*; H22 1(GND)*; TP_BIOS_LABEL 1*; U50 1(NC)*; U51 6(NC0)* 7(NC1)* 8(NC2)* 14(NC3)* 15(NC4)* 16(NC5)*; U81 22(RSVD_22_NC)*; U101 1(NC)*; U105 1(NC)*

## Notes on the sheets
sheet 82
- ISOLATOR_2
sheet 83
- Screw Hole
- Screw
- CE Logo
- WEEE
- Quanta LOGO
- Heatsink HOLE
- ICT Tooling Hole
- PCB VENDOR LOGO
- PCB FREE
- Suction nozzle
- SCREW
sheet 84
- Design Note : Current loading for P1V05_PCH is about 5.3A.
- P1V05_PCH SWITCH
sheet 85
- BLANK
sheet 86
- I2C ADDRESS: 0X80
- Power sensing INA230
sheet 87
- LED0: ACTIVE
  LED1:SPD 100M
  LED2: SPD 1G
- I210 GbE PHY PCIE,MDI
sheet 88
- I210 GbE PHY JTAG,SPI,POWER
sheet 89
- TP RESERVE FOR ICT
sheet 90
- POWER SQUENCE DIAGRAM_2
sheet 91
- BLANK
sheet 92
- 00 = Both LAN ports are disabled. Note: In this mode
  manageability is not functional and must not be enabled in
  NVM control word 1.
  01 = Port 1 is disabled. Port 0 is enabled.
  10 = Reserved
  11 = Both Port 0 and 1 are enabled.
- MDC/MDIO
sheet 93
- PWRGD/RST DIAGRAM
